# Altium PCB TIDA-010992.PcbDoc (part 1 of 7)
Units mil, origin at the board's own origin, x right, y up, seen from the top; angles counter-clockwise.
Board outline 2810.81 x 2427 mil, 8 copper layers (L01-TOP, L02-GND, L03-SIG, L04-GND, L05-PWR, L06-SIG, L07-GND, L08-BOTTOM), stack 61.9 mil thick; 521 components, 377 nets, 1545 pads, 874 vias.
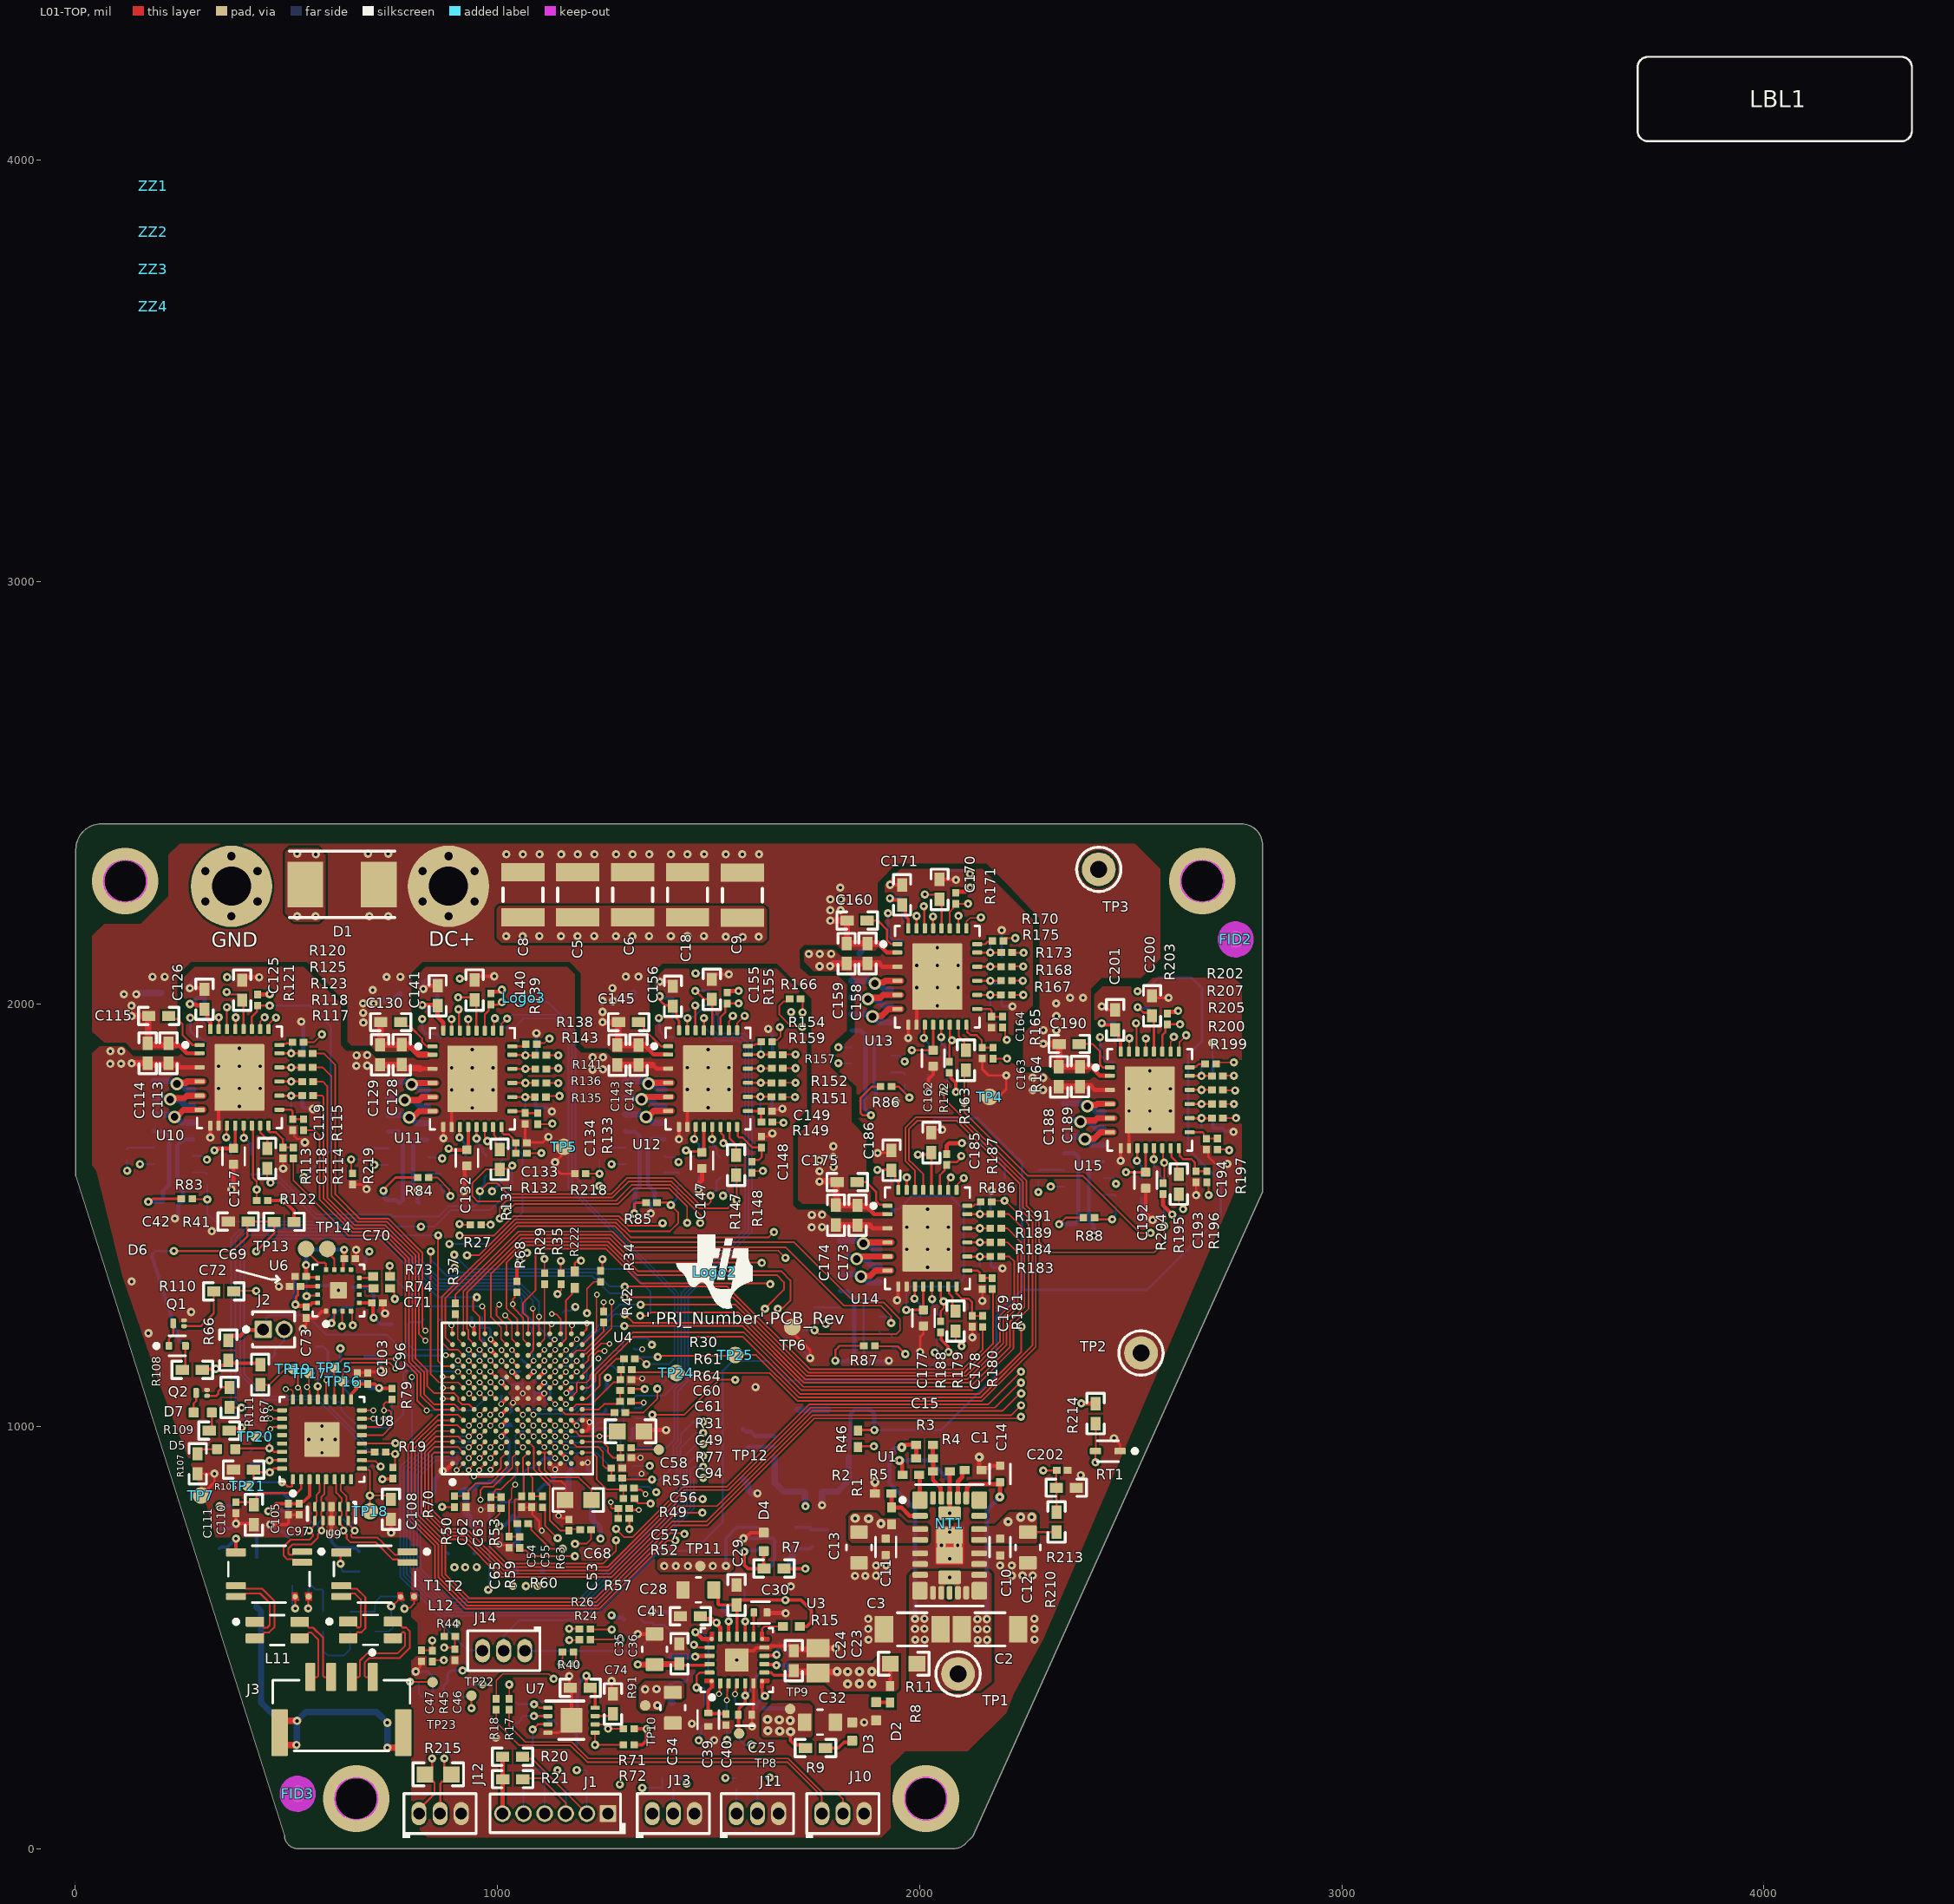
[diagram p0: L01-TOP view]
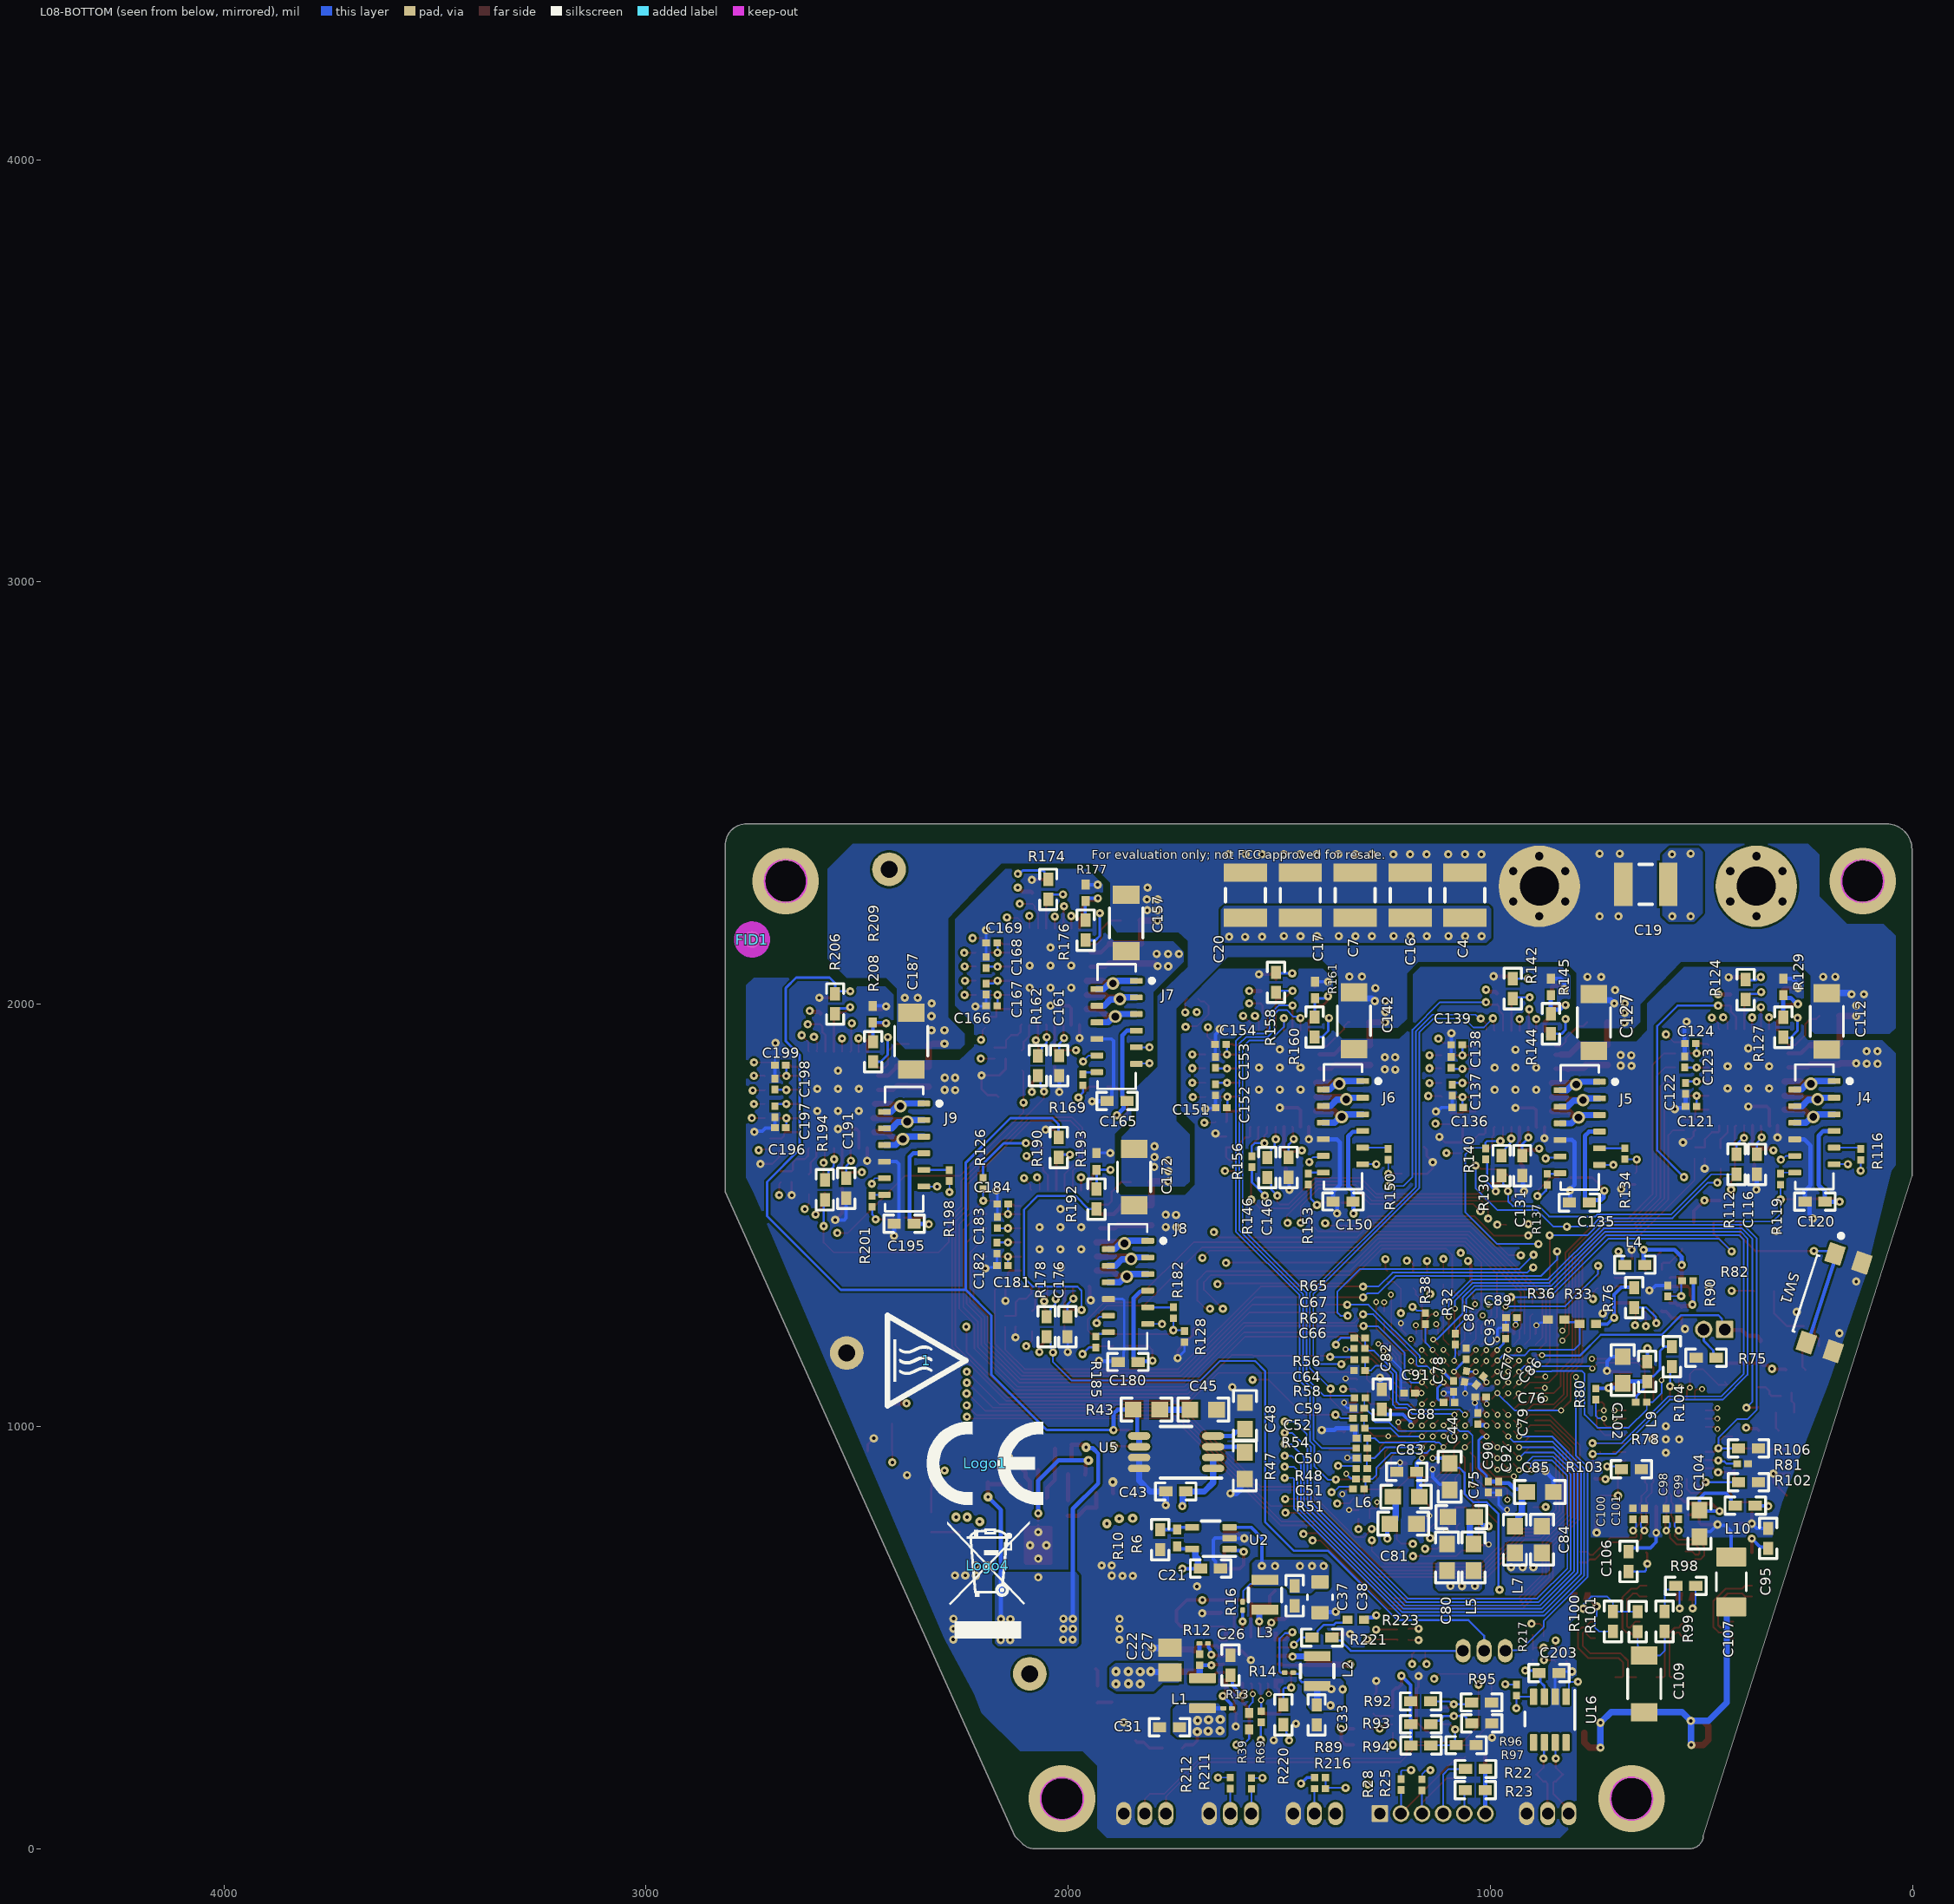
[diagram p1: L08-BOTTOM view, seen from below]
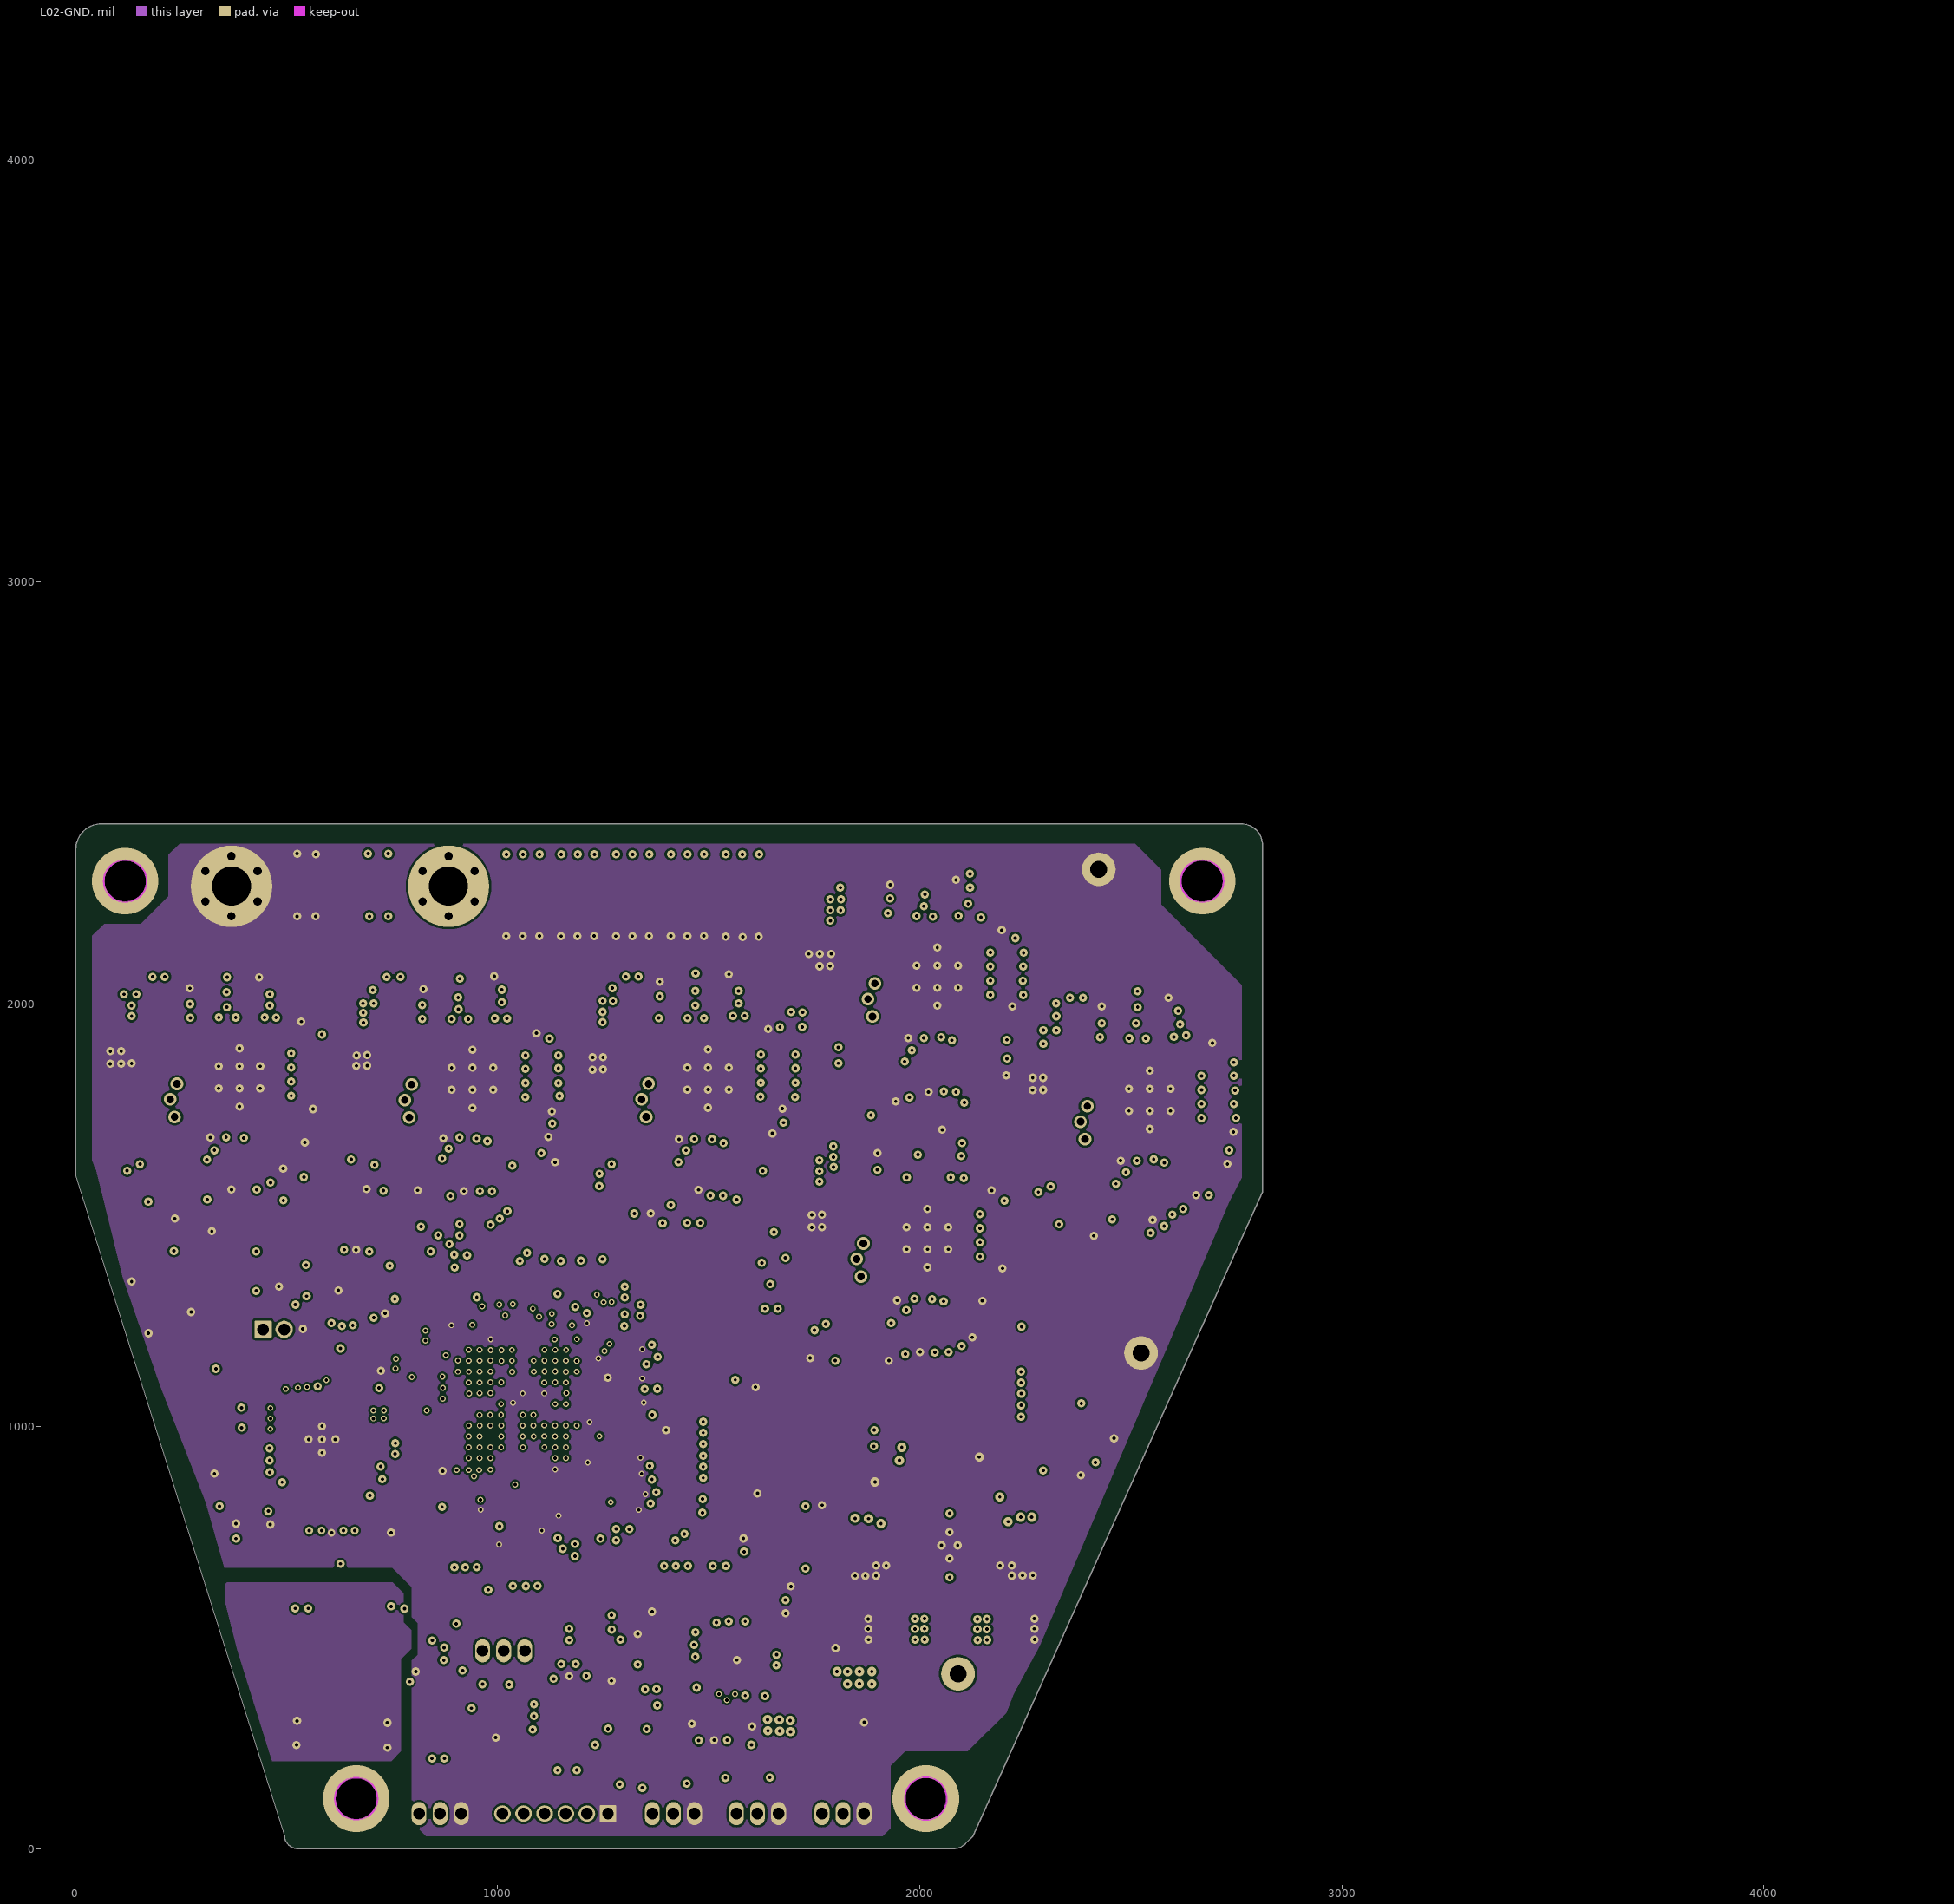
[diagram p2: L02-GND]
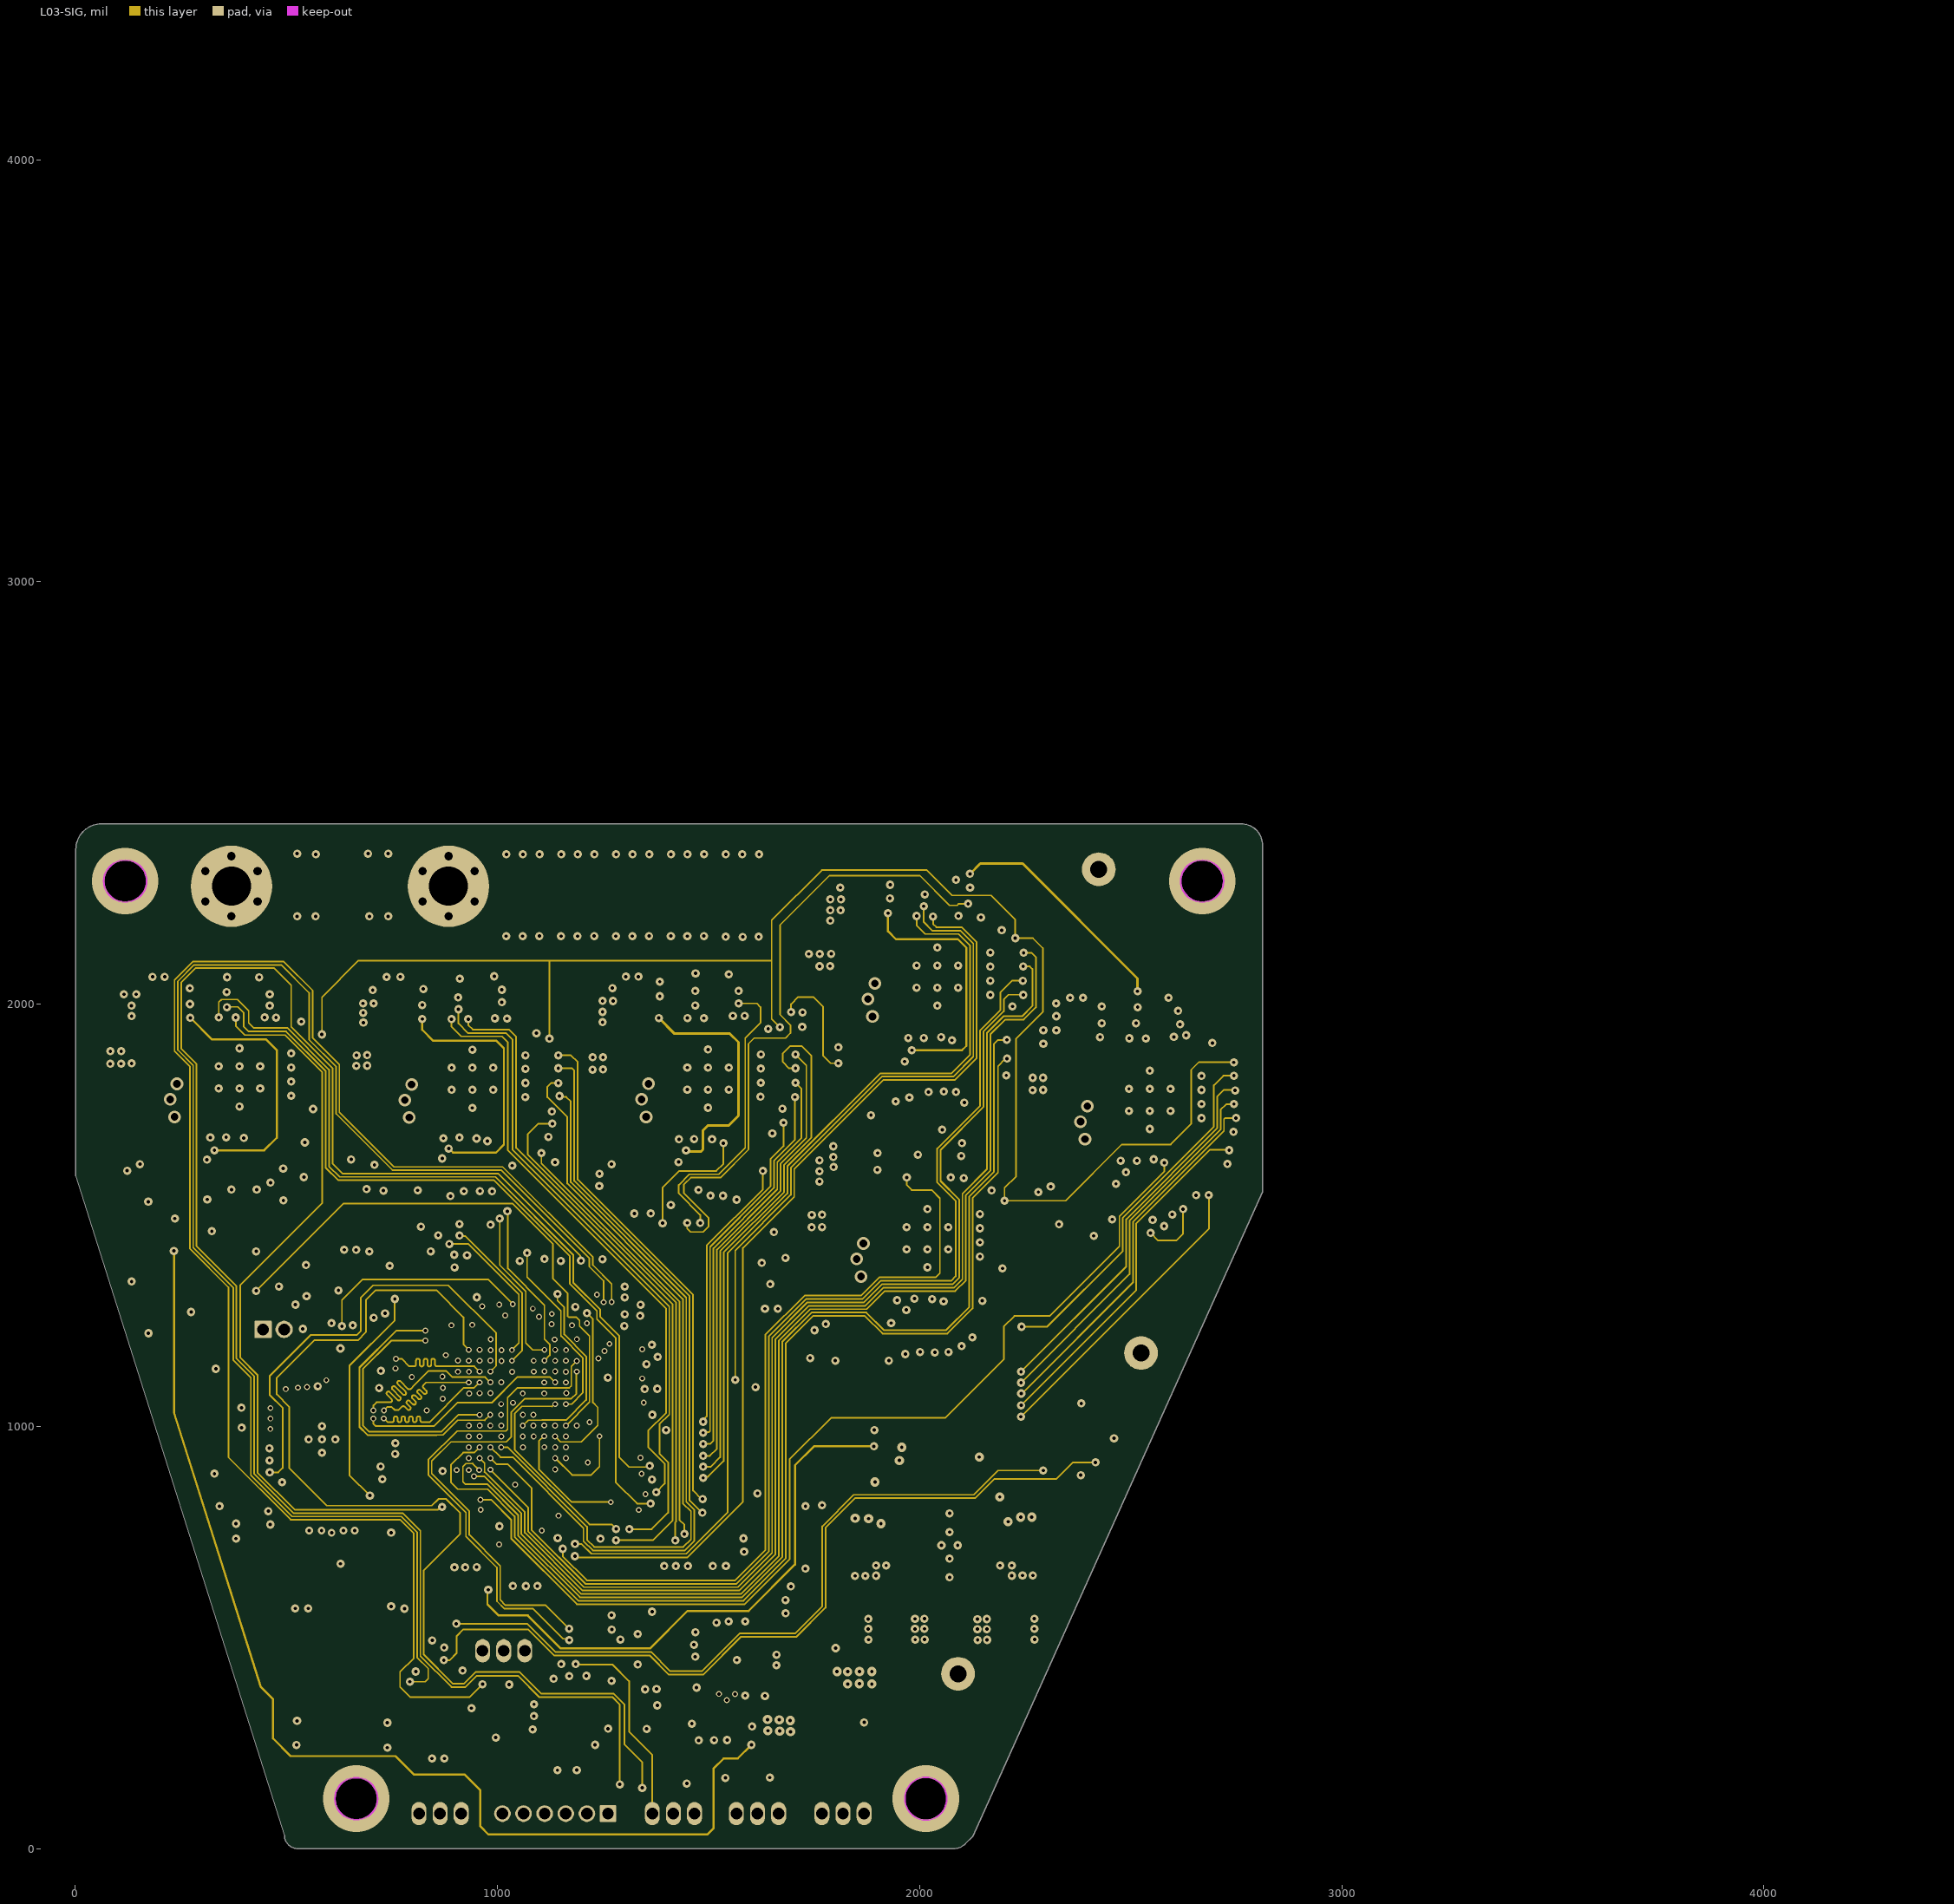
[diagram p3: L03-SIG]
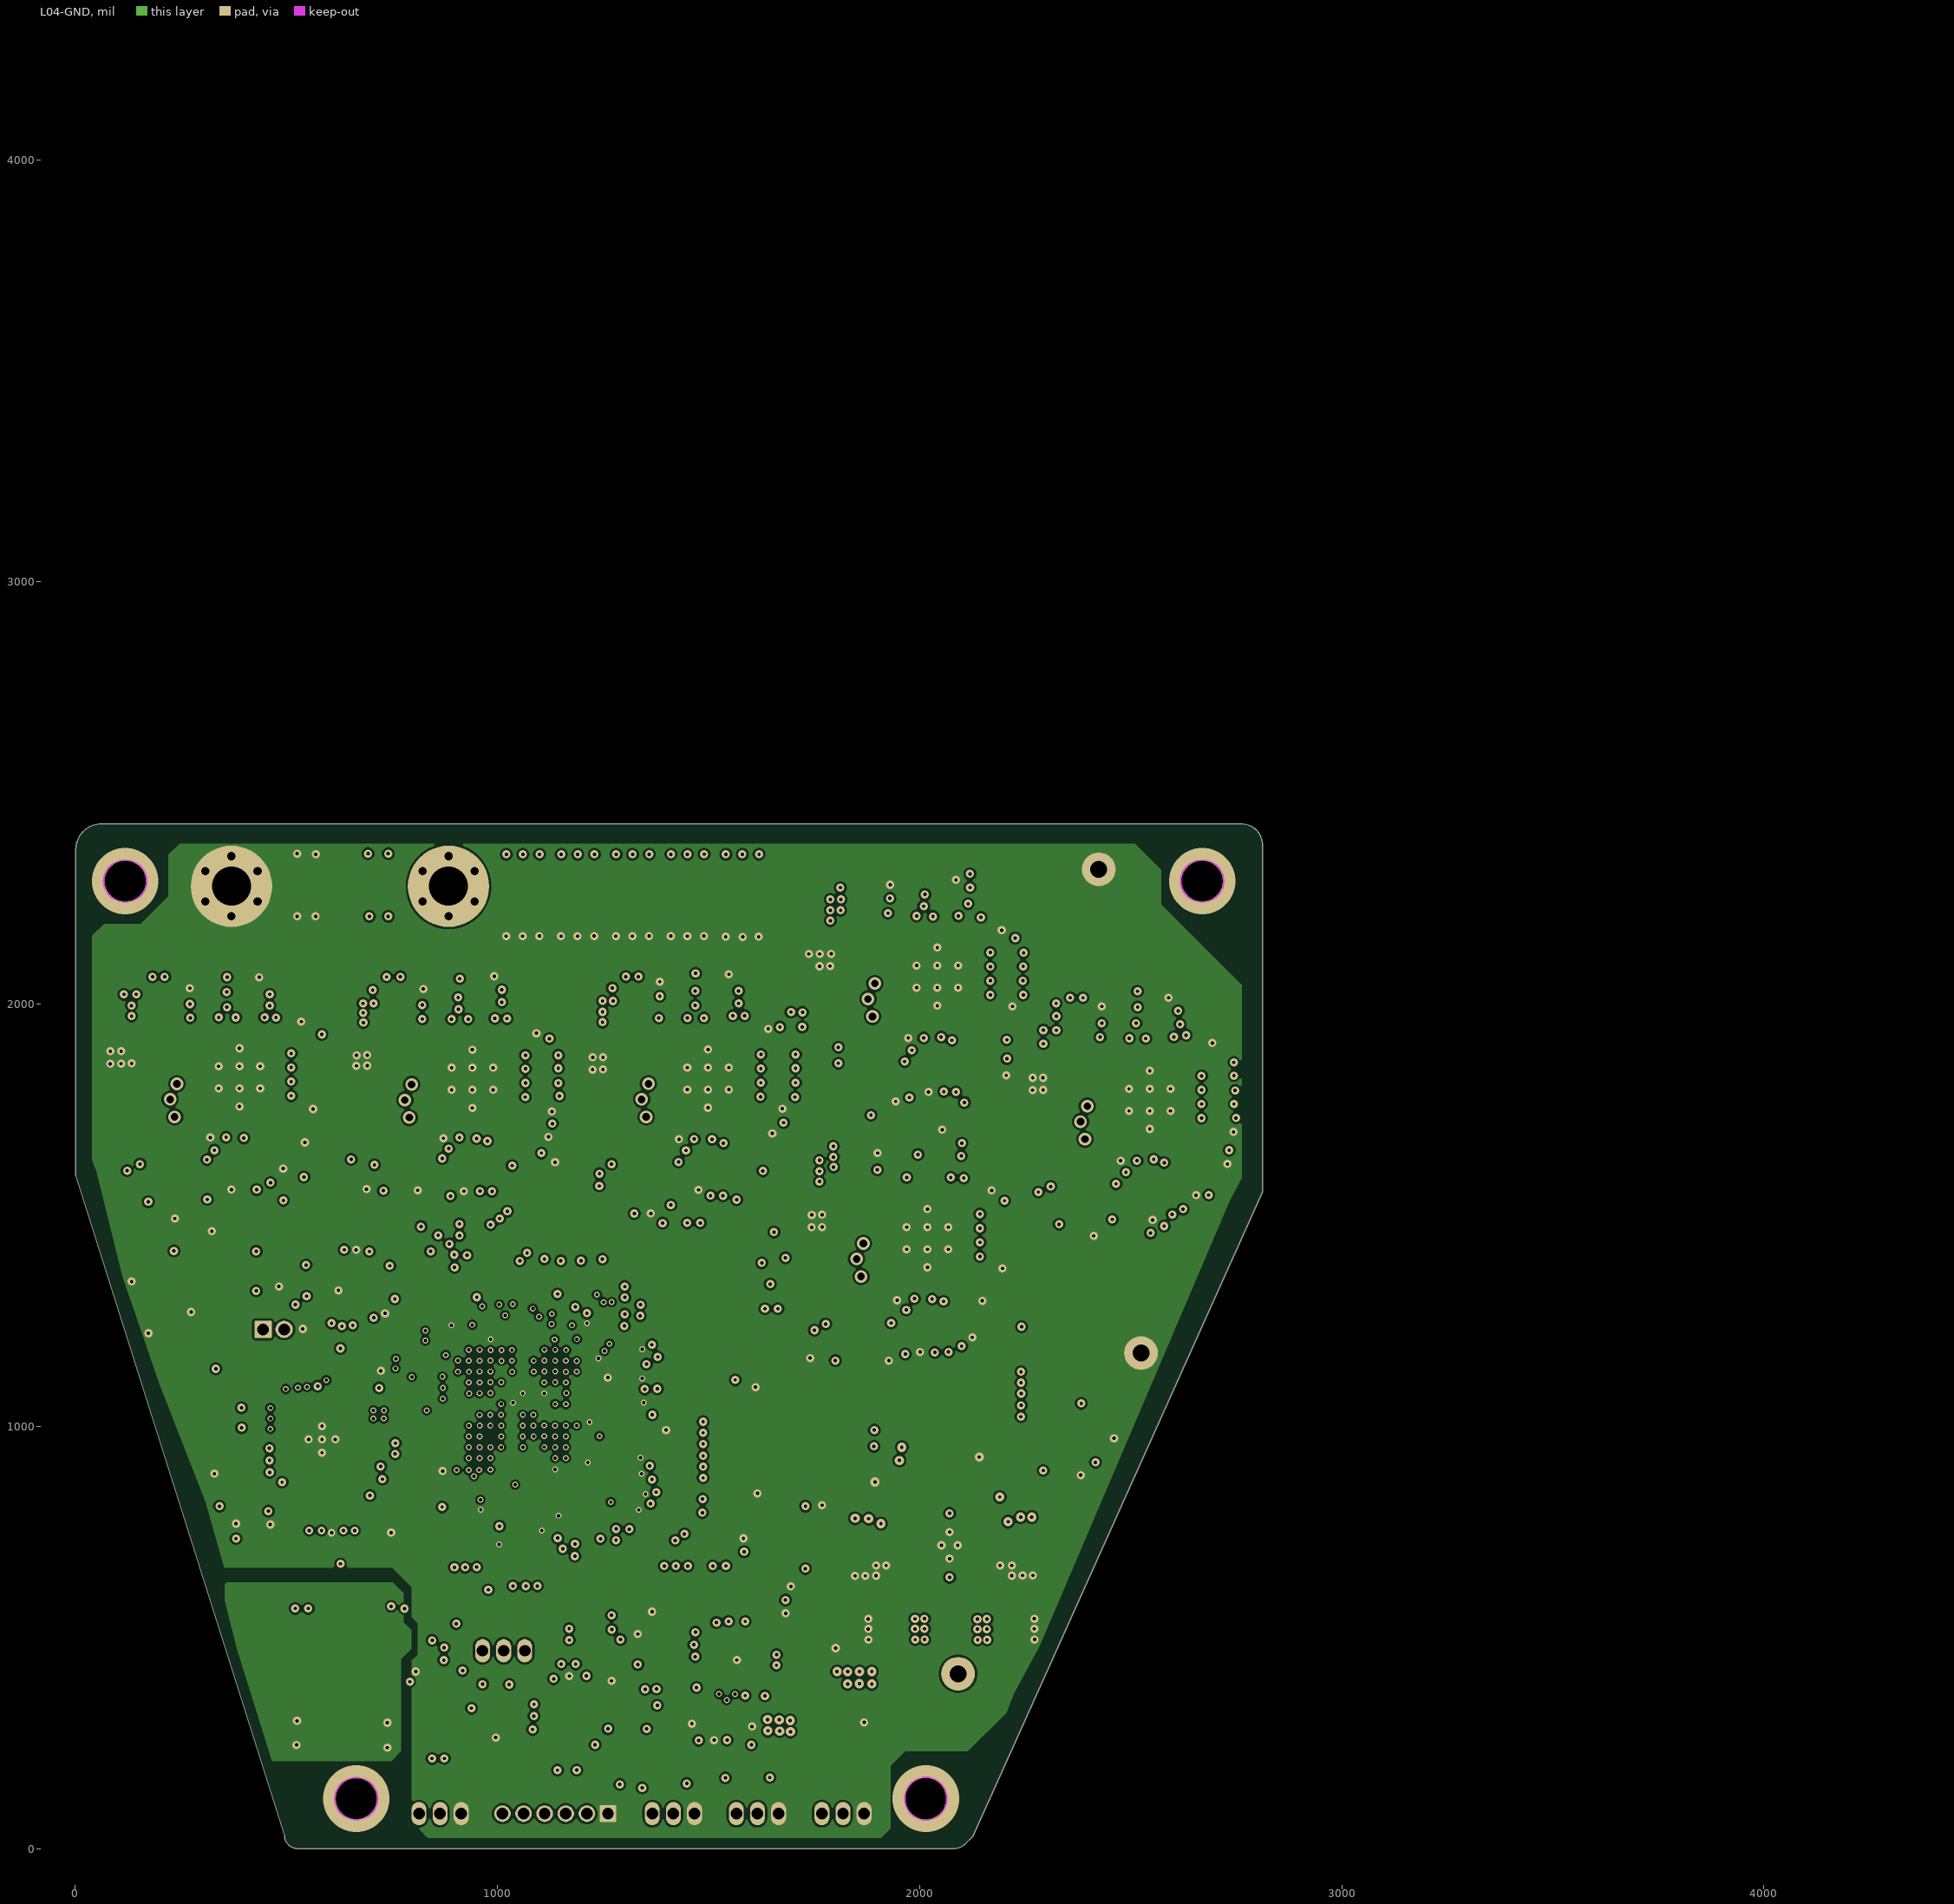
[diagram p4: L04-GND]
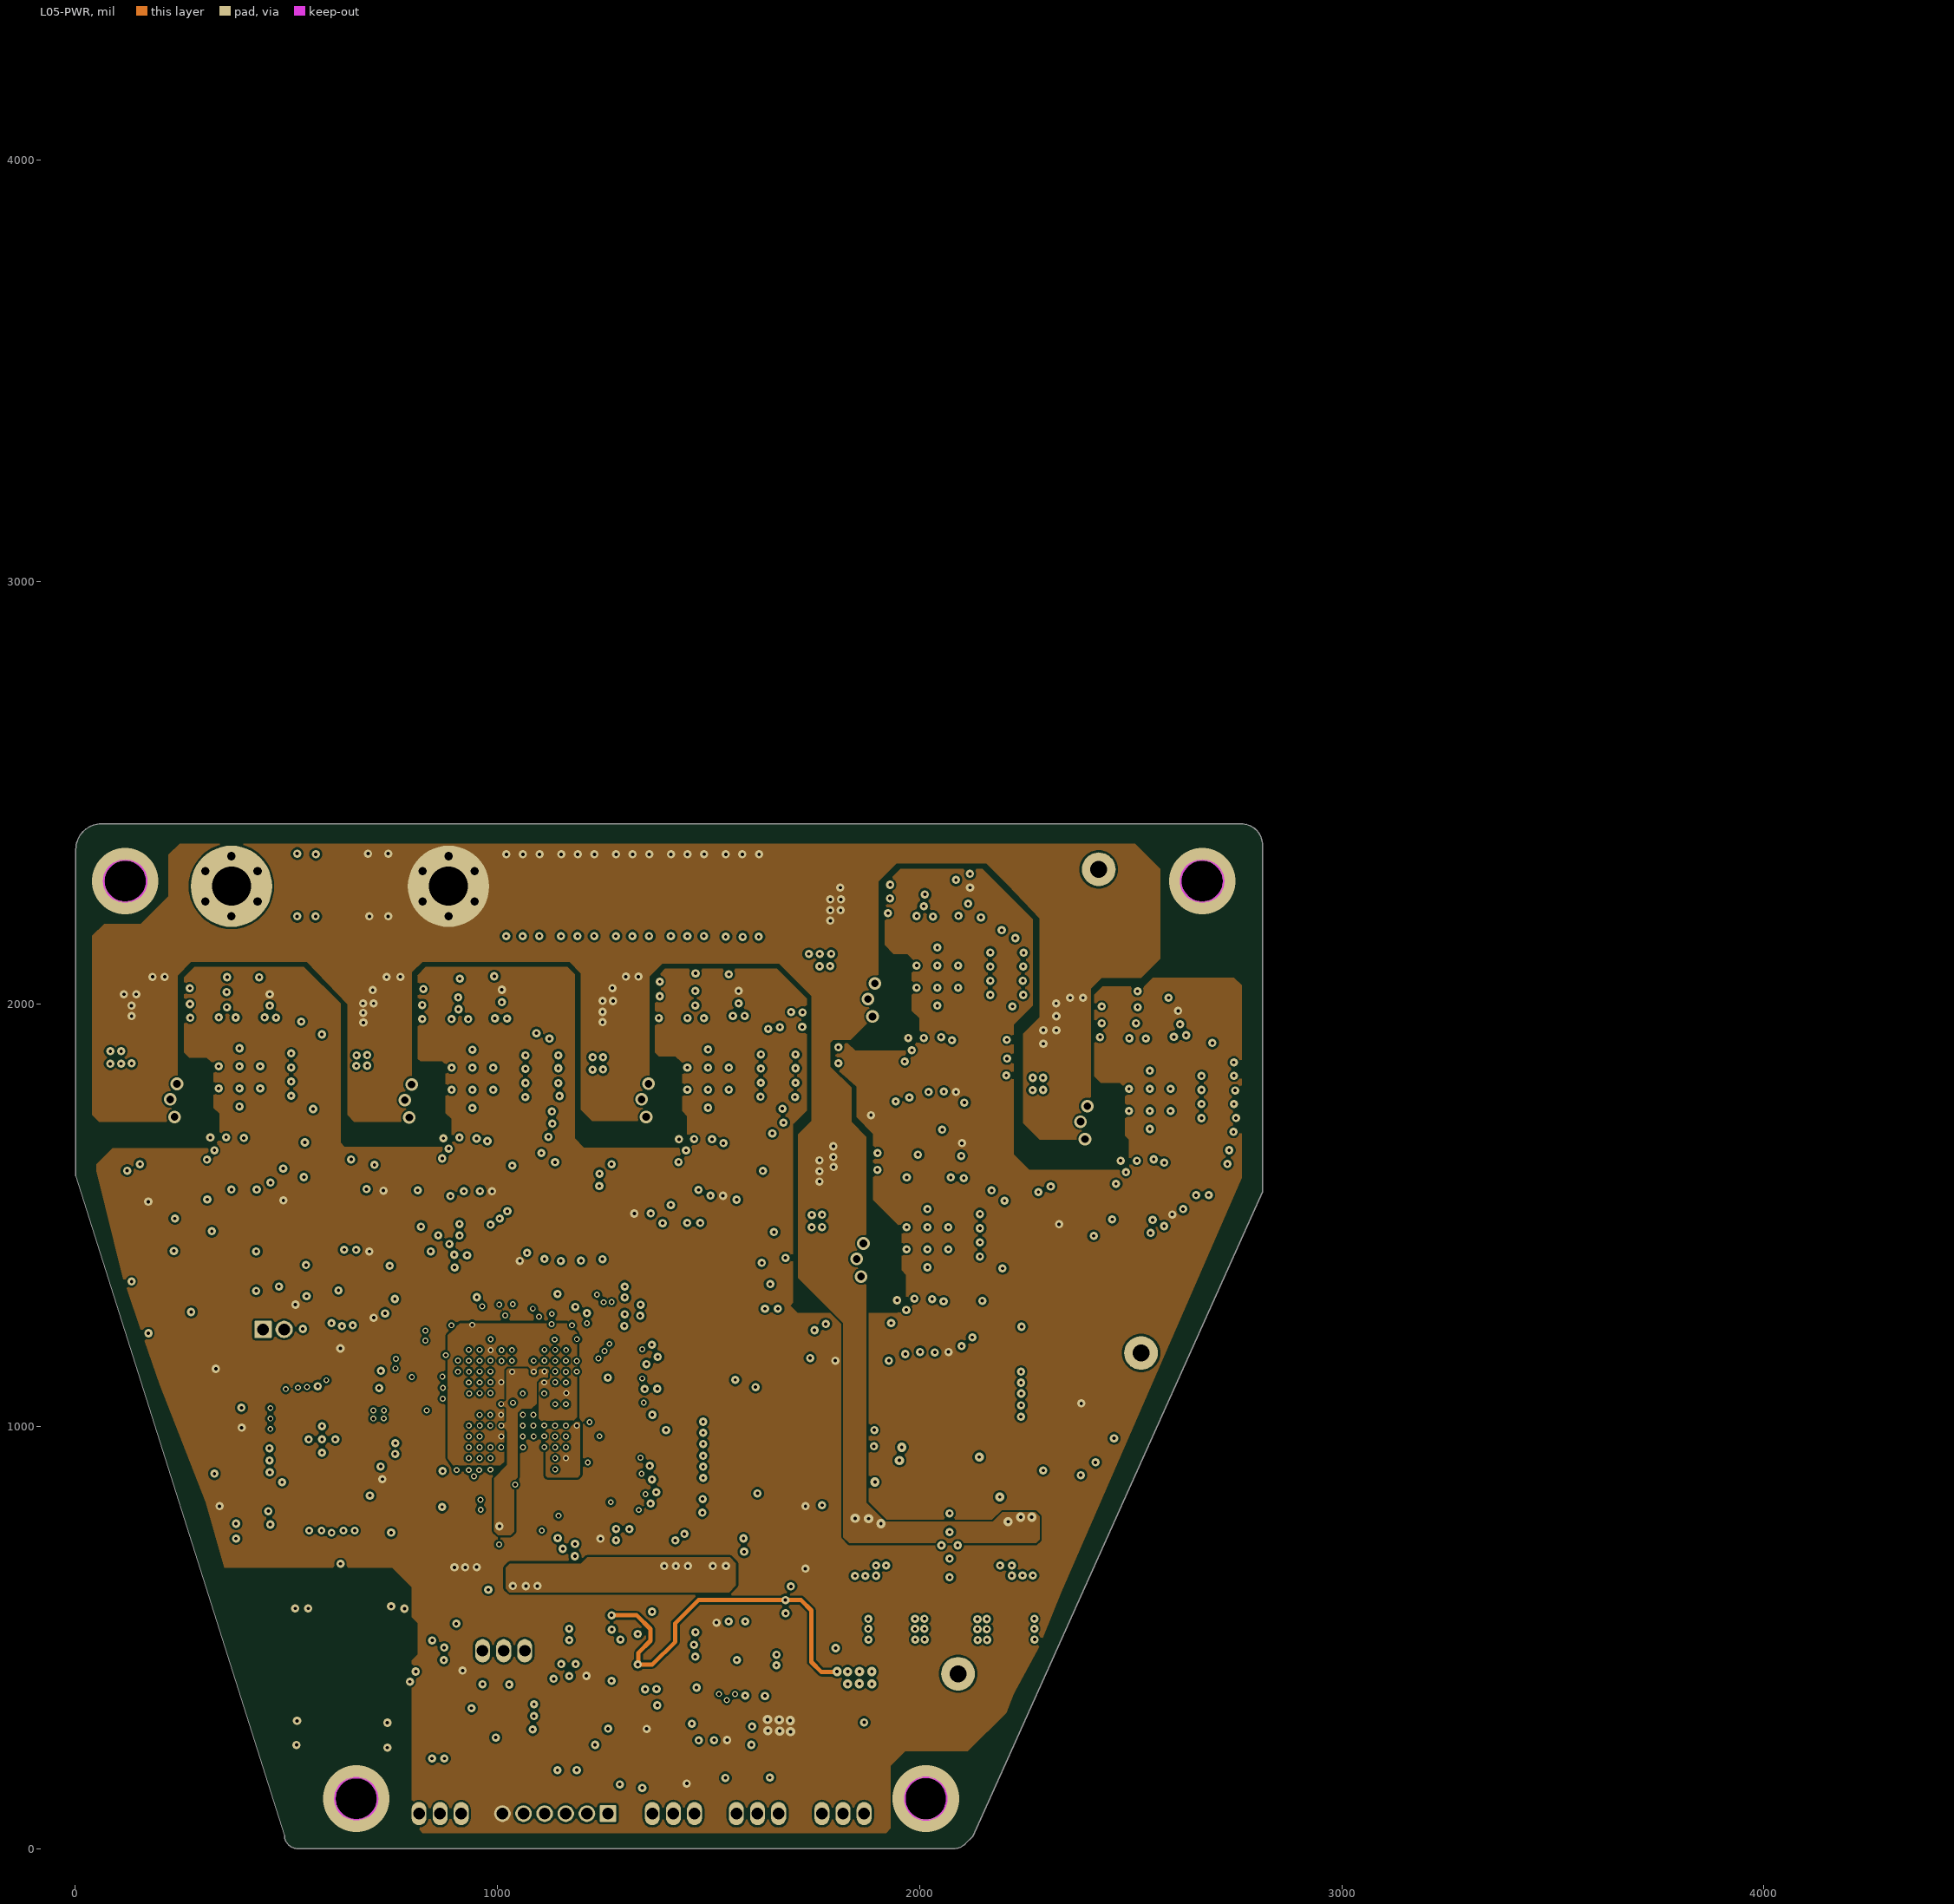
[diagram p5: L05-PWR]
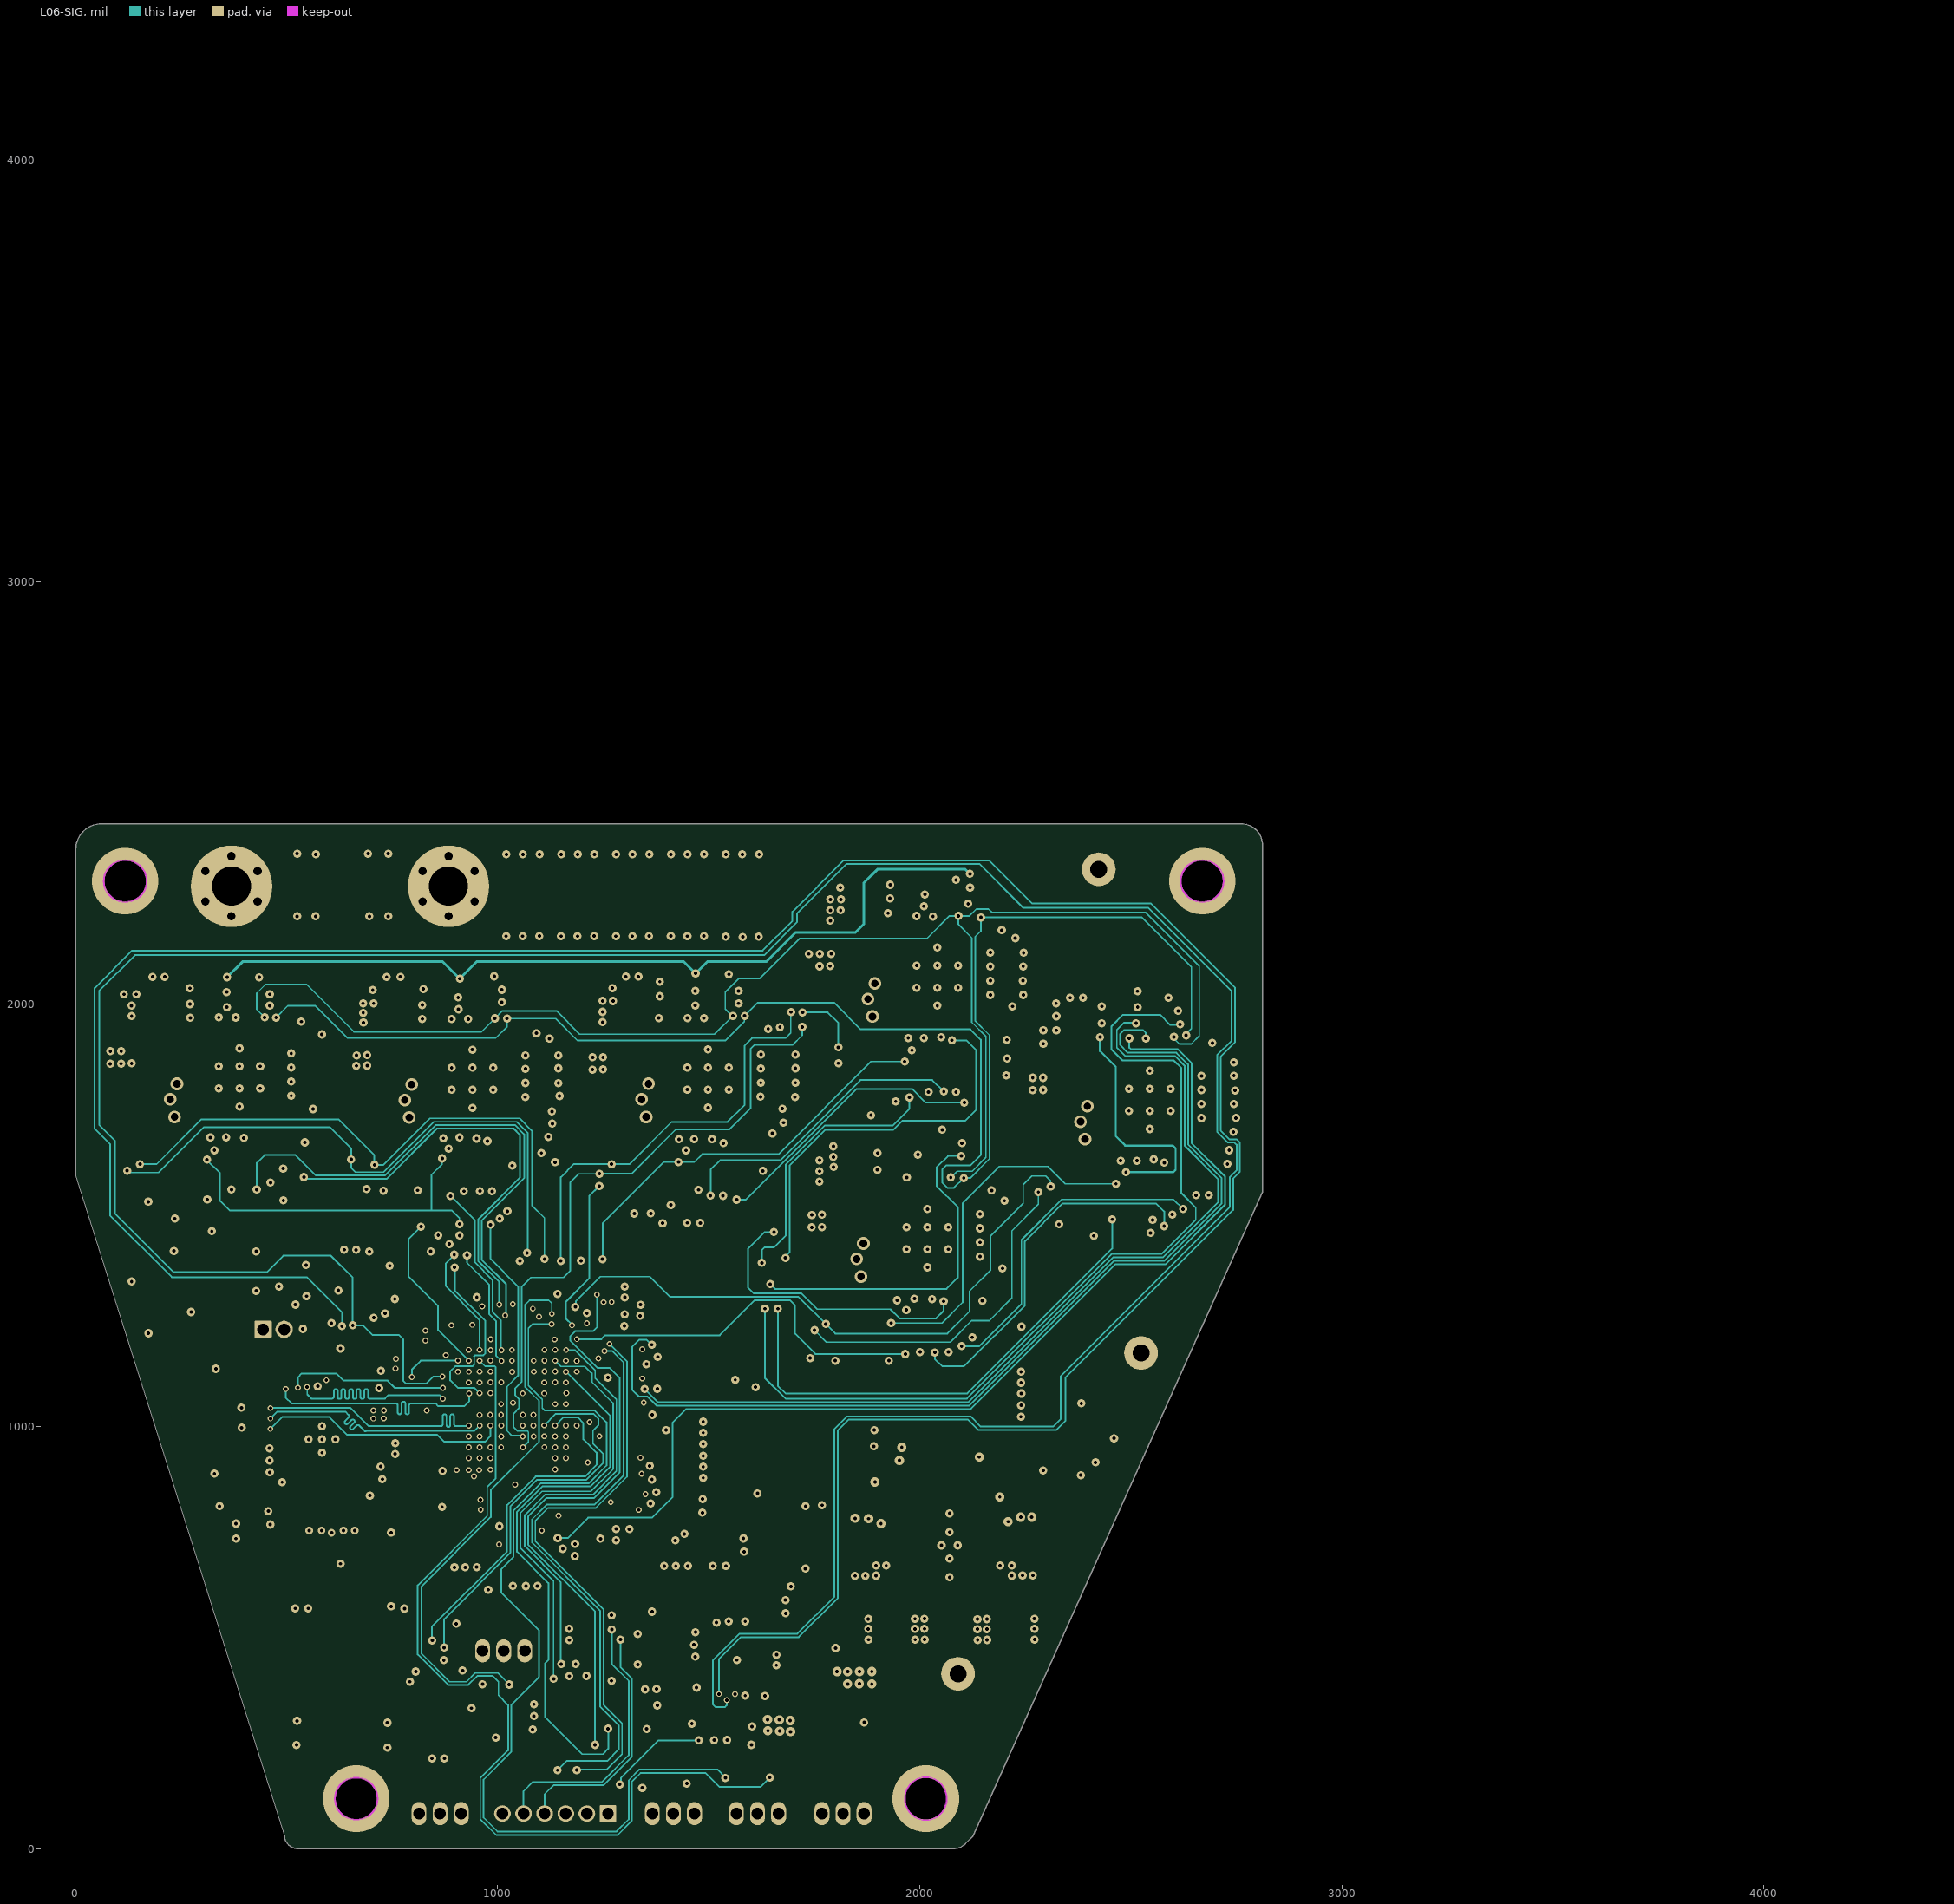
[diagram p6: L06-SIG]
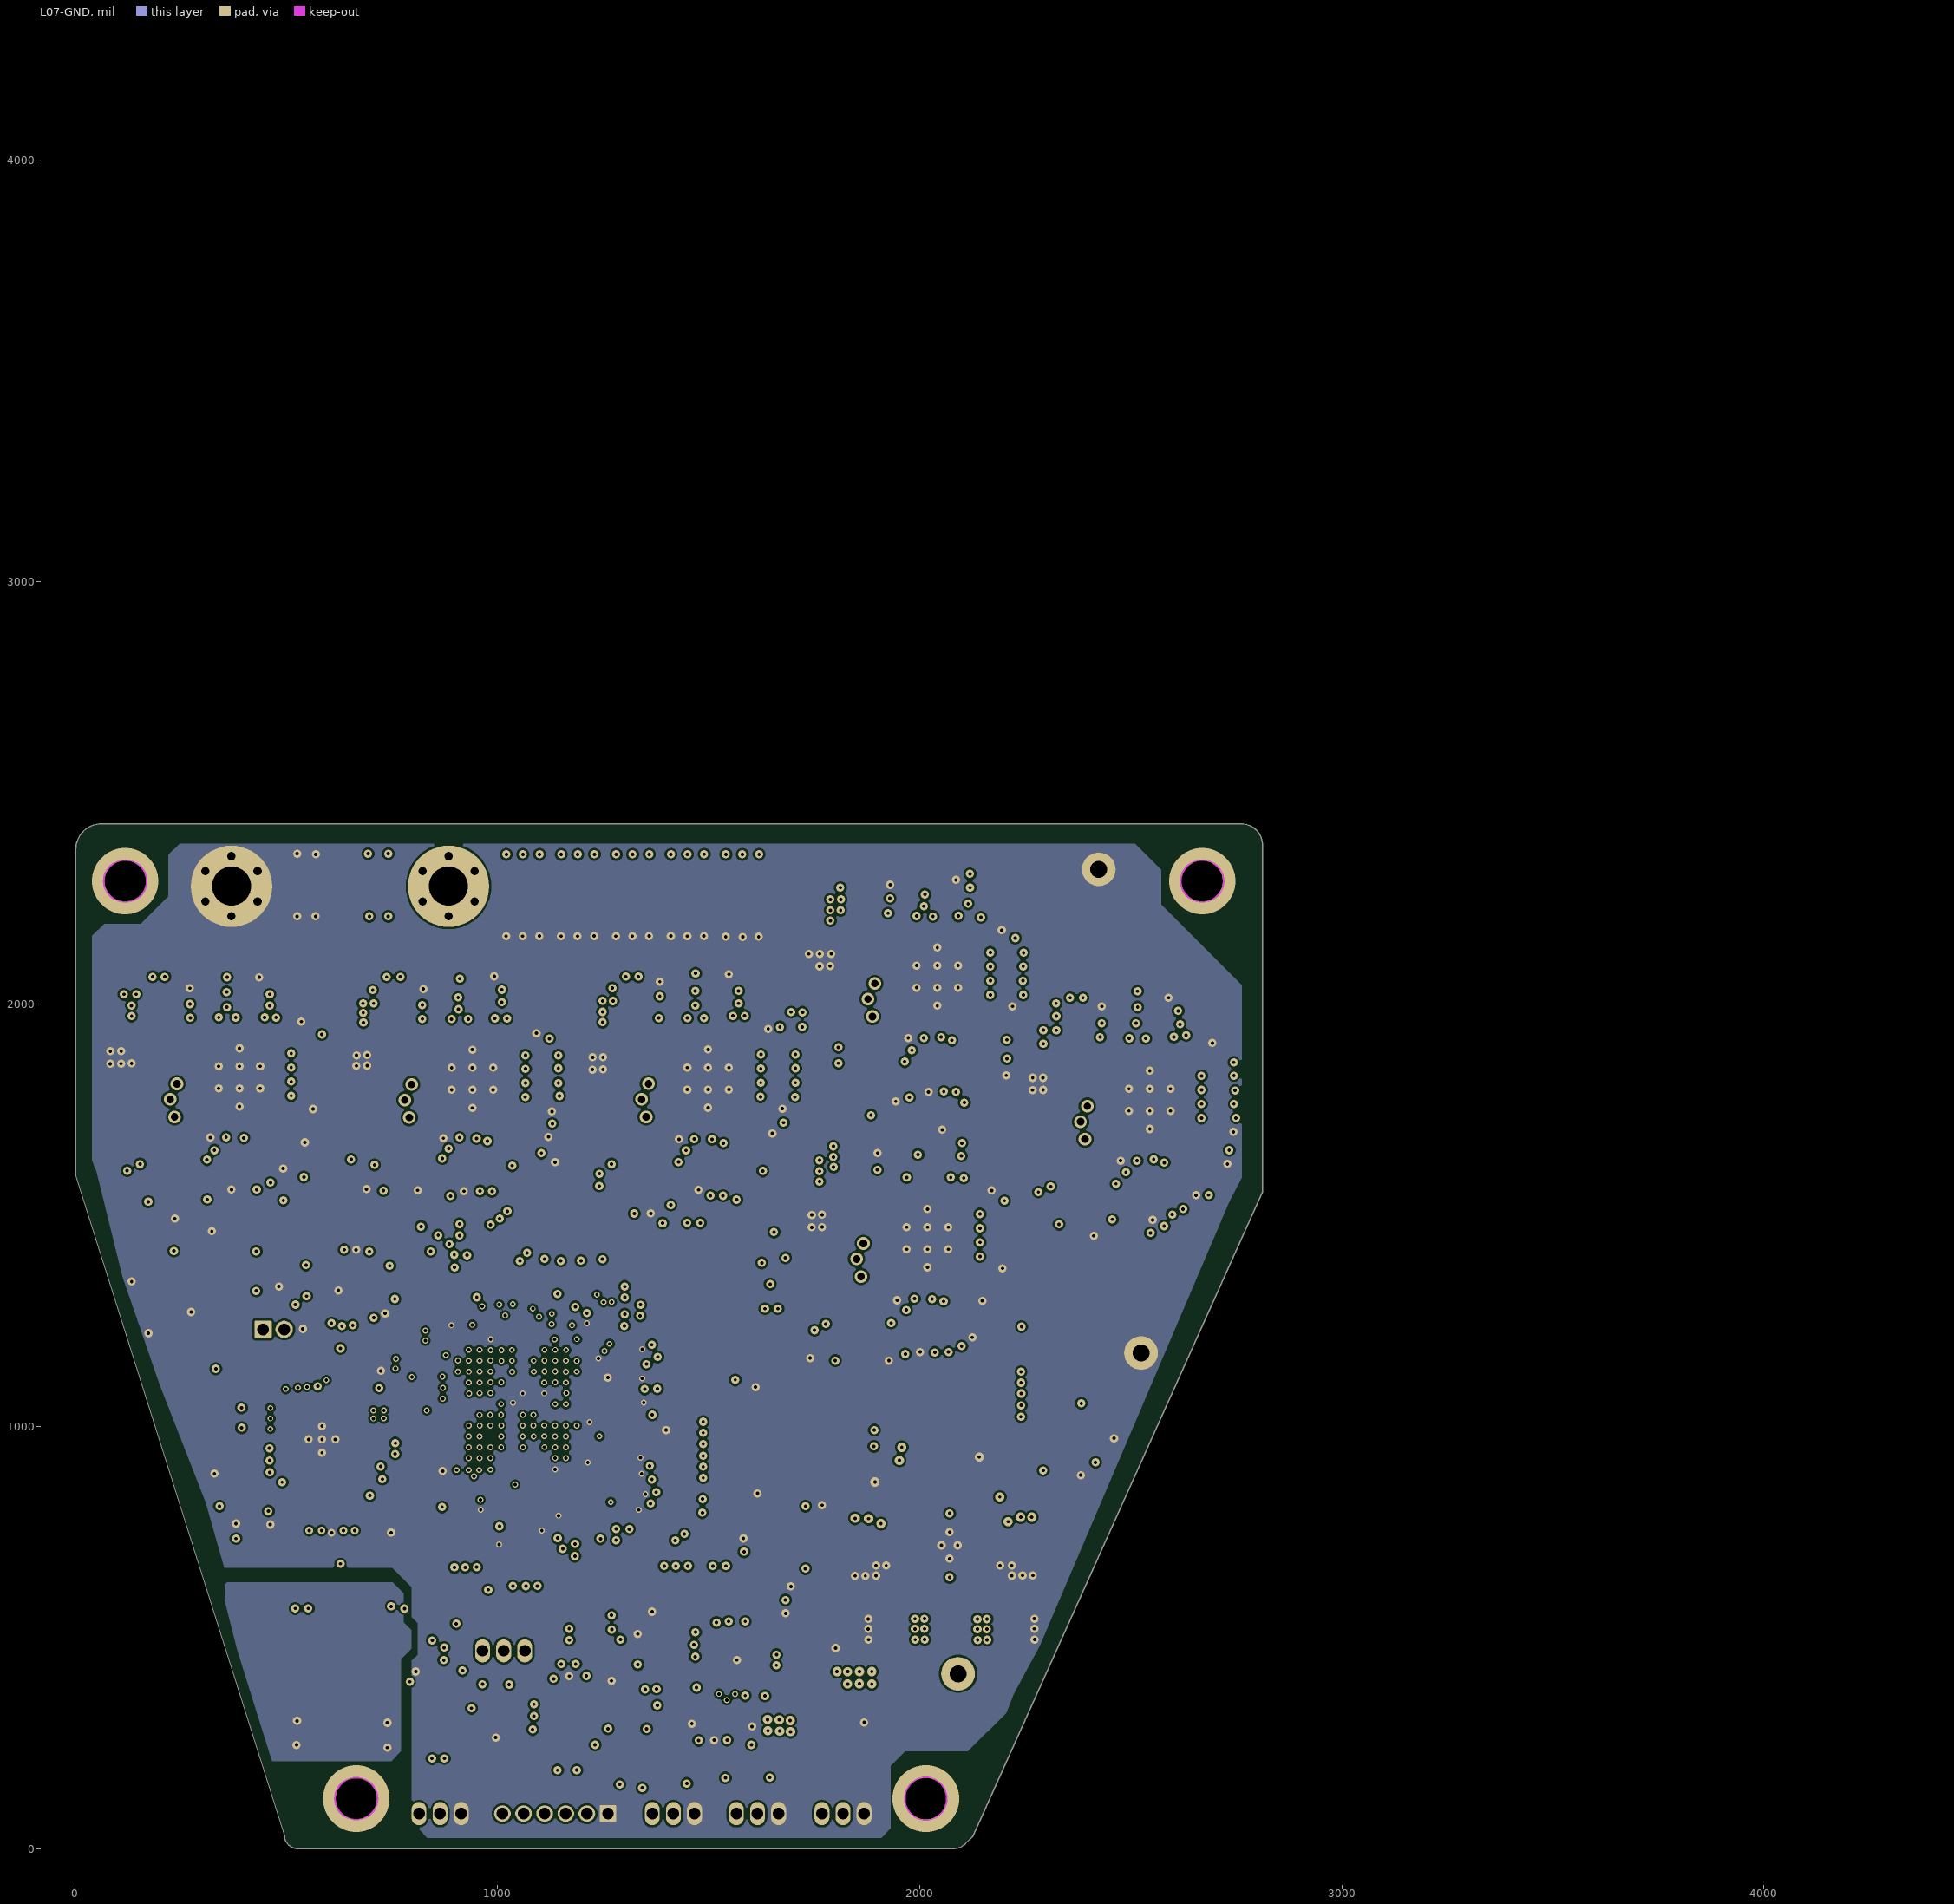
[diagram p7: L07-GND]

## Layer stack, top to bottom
Top Solder: solder mask 0.4, Solder Resist, Dk 3.5
L01-TOP: signal copper 1.4
Dielectric 1: prepreg 3.3, FR-4 370, Dk 4.2
L02-GND: signal copper 1.4
Dielectric 2: core 5, FR-4 370, Dk 4.3
L03-SIG: signal copper 1.4
Dielectric 3: prepreg 9.8, FR-4 370, Dk 4.1
L04-GND: signal copper 1.4
Dielectric 4: core 14.5, FR-4 370, Dk 4.2
L05-PWR: signal copper 1.4
Dielectric 5: prepreg 9.8, FR-4 370, Dk 4.1
L06-SIG: signal copper 1.4
Dielectric 6: core 5, FR-4 370, Dk 4.3
L07-GND: signal copper 1.4
Dielectric 7: prepreg 3.3, FR-4 370, Dk 4.2
L08-BOTTOM: signal copper 1.4
Bottom Solder: solder mask 0.4, Solder Resist, Dk 3.5

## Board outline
526.76,0 cw(c526.76,31.41) 495.35,31.41 1.19,1592.72 1.19,2366.47 cw(c61.71,2366.47) 61.71,2427 2739,2427 2762,2427 cw(c2762,2377) 2812,2377 2811.97,1555 2126,29 2108.31,11.31 cw(c2081,38.63) 2081,0 2034.41,0 529,0
cut-out: 2669.29,2240.16 cw(c2669.29,2291.34) 2618.11,2291.34 cw(c2669.29,2291.34) 2669.29,2342.52 cw(c2669.29,2291.34) 2720.47,2291.34 cw(c2669.29,2291.34)
cut-out: 1963.39,118.11 ccw(c2014.57,118.11) 2014.57,66.93 ccw(c2014.57,118.11) 2065.75,118.11 ccw(c2014.57,118.11) 2014.57,169.29 ccw(c2014.57,118.11)
cut-out: 118.11,2240.16 cw(c118.11,2291.34) 66.93,2291.34 cw(c118.11,2291.34) 118.11,2342.52 cw(c118.11,2291.34) 169.29,2291.34 cw(c118.11,2291.34)
cut-out: 665.35,66.93 cw(c665.35,118.11) 614.17,118.11 cw(c665.35,118.11) 665.35,169.29 cw(c665.35,118.11) 716.54,118.11 cw(c665.35,118.11)
cut-out: 2669.29,2240.16 cw(c2669.29,2291.34) 2618.11,2291.34 cw(c2669.29,2291.34) 2669.29,2342.52 cw(c2669.29,2291.34) 2720.47,2291.34 cw(c2669.29,2291.34)
cut-out: 1963.39,118.11 ccw(c2014.57,118.11) 2014.57,66.93 ccw(c2014.57,118.11) 2065.75,118.11 ccw(c2014.57,118.11) 2014.57,169.29 ccw(c2014.57,118.11)
cut-out: 118.11,2240.16 cw(c118.11,2291.34) 66.93,2291.34 cw(c118.11,2291.34) 118.11,2342.52 cw(c118.11,2291.34) 169.29,2291.34 cw(c118.11,2291.34)
cut-out: 665.35,66.93 cw(c665.35,118.11) 614.17,118.11 cw(c665.35,118.11) 665.35,169.29 cw(c665.35,118.11) 716.54,118.11 cw(c665.35,118.11)
cut-out: 2669.29,2242.13 cw(c2669.29,2291.34) 2620.08,2291.34 cw(c2669.29,2291.34) 2669.29,2340.55 cw(c2669.29,2291.34) 2718.5,2291.34 cw(c2669.29,2291.34)
cut-out: 1965.35,118.11 ccw(c2014.57,118.11) 2014.57,68.9 ccw(c2014.57,118.11) 2063.78,118.11 ccw(c2014.57,118.11) 2014.57,167.32 ccw(c2014.57,118.11)
cut-out: 118.11,2242.13 cw(c118.11,2291.34) 68.9,2291.34 cw(c118.11,2291.34) 118.11,2340.55 cw(c118.11,2291.34) 167.32,2291.34 cw(c118.11,2291.34)
cut-out: 665.35,68.9 cw(c665.35,118.11) 616.14,118.11 cw(c665.35,118.11) 665.35,167.32 cw(c665.35,118.11) 714.57,118.11 cw(c665.35,118.11)

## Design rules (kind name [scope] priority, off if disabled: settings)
AcuteAngle [All] p1: minimum=4.50000000000000E+0001 checktracksonly=TRUE
AcuteAngle AcuteAngle_poly [InPolygon] p2: minimum=4.50000000000000E+0001 checktracksonly=FALSE
AssemblyTestPointUsage [All] p1: valid=2
BoardOutlineClearance BoardOutlineClearance_USB1 [InComponent('USB1')] p1: gap=0 ignorepadtopadclearanceinfootprint=FALSE
BoardOutlineClearance BoardOutlineClearance_MountingHoles [OnCopper and InComponentClass('Mounting Holes')] p2: gap=40 ignorepadtopadclearanceinfootprint=FALSE
BoardOutlineClearance BoardOutlineClearance_Poly [OnCopper and IsPoly] p3: gap=25 ignorepadtopadclearanceinfootprint=FALSE
BoardOutlineClearance [OnCopper and Not InComponentClass('Logo') and not InComponentClass('FiducialMark') and not InRegion(1000,500,4000,800) and not InPoly] p4: gap=10 ignorepadtopadclearanceinfootprint=FALSE
Clearance Poly [InPolygon] p1: gap=5 ignorepadtopadclearanceinfootprint=FALSE
Clearance "RJ45 pad" [InComponent('RJ1') OR InComponent('RJ2')] p2: gap=5 ignorepadtopadclearanceinfootprint=TRUE except(0: SMDPad-THPad)
Clearance Keepout [((IsTrack Or IsArc) And Not InPoly) And IsFree and IsKeepOut vs ((IsTrack Or IsArc) And Not InPoly) And IsFree and IsKeepOut] p3: gap=5 ignorepadtopadclearanceinfootprint=FALSE
Clearance USB1 [InComponent('USB1') vs OnLayer('Keep-Out Layer')] p4: gap=7.87 ignorepadtopadclearanceinfootprint=FALSE
Clearance ISVIA [ISVIA vs ISVIA] p5: gap=0.2 ignorepadtopadclearanceinfootprint=FALSE
Clearance Clearance_FiducialMark [IsKeepOut and InComponentClass('FiducialMark') vs IsPad and InComponentClass('FiducialMark')] p6: gap=0 ignorepadtopadclearanceinfootprint=FALSE
Clearance Clearance_Boardedge [All vs IsKeepOut] p7: gap=11.81 ignorepadtopadclearanceinfootprint=FALSE
Clearance INPOLYGON [InPolygon] p8: gap=11.91 ignorepadtopadclearanceinfootprint=FALSE
Clearance [All] p9: gap=5 ignorepadtopadclearanceinfootprint=FALSE except(3.7: Arc-Via Track-Via; 4: Arc-Arc Arc-Track Arc-SMDPad Track-Track Track-SMDPad)
ComponentClearance "ComponentClearance_overlay to overlay" [OnBottomSilkscreen vs OnTopSilkscreen] p1: gap=0 collisioncheckmode=3 verticalgap=0 showdistances=FALSE
ComponentClearance ComponentClearance_MountingHoles_FiducialMarks [InComponentClass('Mounting Holes') vs InComponentClass('FiducialMark')] p2: gap=10 collisioncheckmode=3 verticalgap=10 showdistances=FALSE
ComponentClearance ComponentClearance_Shunt [InComponentClass('Header') vs InComponentClass('Shunt')] p3: gap=0 collisioncheckmode=3 verticalgap=0 showdistances=FALSE
ComponentClearance ComponentClearance_Logo [InComponentClass('Logo')] p4: gap=10 collisioncheckmode=3 verticalgap=10 showdistances=FALSE
ComponentClearance ComponentClearance_ScrewToNut [(HasFootprint('NY PMS 440 0025 PH')) vs (HasFootprint('Keystone_1902C'))] p5: gap=5 collisioncheckmode=3 verticalgap=10 showdistances=FALSE
ComponentClearance ComponentClearance_MountingHoles [InComponentClass('Mounting Holes')] p6 off: gap=250 collisioncheckmode=3 verticalgap=100000 showdistances=FALSE
ComponentClearance ComponentClearance_SmallPassives [HasFootprint('0201*') or HasFootprint('0402*') or HasFootprint('0508') or HasFootprint('0603*') or HasFootprint('0612') or HasFootprint('0805*') or HasFootprint('0815*') or HasFootprint('0830*') or HasFootprint('1206*') or HasFootprint('1210*') or HasFootprint('1808*') or HasFootprint('1812*') or HasFootprint('1825*') or HasFootprint('2010*') or HasFootprint('2220*') or HasFootprint('2225*') or HasFootprint('2512*') or HasFootprint('2728*') or HasFootprint('3518*') vs HasFootprint('0201*') or HasFootprint('0402*') or HasFootprint('0508') or HasFootprint('0603*') or HasFootprint('0612') or HasFootprint('0805*') or HasFootprint('0815*') or HasFootprint('0830*') or HasFootprint('1206*') or HasFootprint('1210*') or HasFootprint('1808*') or HasFootprint('1812*') or HasFootprint('1825*') or HasFootprint('2010*') or HasFootprint('2220*') or HasFootprint('2225*') or HasFootprint('2512*') or HasFootprint('2728*') or HasFootprint('3518*')] p7 off: gap=10 collisioncheckmode=3 verticalgap=0 showdistances=FALSE
ComponentClearance ComponentClearance_THtoSMT [IsThruComponent vs IsSMTComponent] p8 off: gap=30 collisioncheckmode=3 verticalgap=30 showdistances=FALSE
ComponentClearance ComponentClearance_THtoTH [IsThruComponent vs IsThruComponent] p9 off: gap=30 collisioncheckmode=3 verticalgap=30 showdistances=FALSE
DiffPairsRouting DiffPairsRouting_100 [All] p1: maxlimit=6.95 minlimit=6.95 mostfreqgap=6.95 toplayer_minwidth=4.25 toplayer_maxwidth=4.25 toplayer_prefwidth=4.25 midlayer1_minwidth=4.25 midlayer1_maxwidth=4.25 midlayer1_prefwidth=4.25 midlayer2_minwidth=4.25 midlayer2_maxwidth=4.25 midlayer2_prefwidth=4.25 midlayer3_minwidth=4.25 midlayer3_maxwidth=4.25 midlayer3_prefwidth=4.25 midlayer4_minwidth=4.25 midlayer4_maxwidth=4.25 midlayer4_prefwidth=4.25 midlayer5_minwidth=4.25 midlayer5_maxwidth=4.25 midlayer5_prefwidth=4.25 midlayer6_minwidth=4.25 midlayer6_maxwidth=4.25 midlayer6_prefwidth=4.25 bottomlayer_minwidth=4.25 bottomlayer_maxwidth=4.25 bottomlayer_prefwidth=4.25 maxuncoupledlength=500
DiffPairsRouting DiffPairsRouting_120 [InDifferentialPairClass('diff120')] p2 off: maxlimit=6.8 minlimit=6.8 mostfreqgap=6.8 toplayer_minwidth=4.1 toplayer_maxwidth=4.1 toplayer_prefwidth=4.1 midlayer1_minwidth=4.1 midlayer1_maxwidth=4.1 midlayer1_prefwidth=4.1 midlayer2_minwidth=4.1 midlayer2_maxwidth=4.1 midlayer2_prefwidth=4.1 midlayer3_minwidth=4.1 midlayer3_maxwidth=4.1 midlayer3_prefwidth=4.1 midlayer4_minwidth=4.1 midlayer4_maxwidth=4.1 midlayer4_prefwidth=4.1 midlayer5_minwidth=4.1 midlayer5_maxwidth=4.1 midlayer5_prefwidth=4.1 midlayer6_minwidth=4.1 midlayer6_maxwidth=4.1 midlayer6_prefwidth=4.1 bottomlayer_minwidth=4.1 bottomlayer_maxwidth=4.1 bottomlayer_prefwidth=4.1 maxuncoupledlength=1000
FabricationTestPointUsage TestPointUsage [All] p1: valid=2 allowmultiple=FALSE
FabricationTestpoint Testpoint [All] p1: side=3 testpointundercomponent=TRUE minsize=40 maxsize=100 preferedsize=60 minholesize=0 maxholesize=40 preferedholesize=32 testpointgrid=1 allowsidetop=TRUE allowsidebottom=TRUE usegrid=TRUE gridtolerance=0.01
FanoutControl Fanout_LCC [IsLCC] p1: bgadir=Out bgaviamode=Centered fanoutstyle=Auto fanoutdirection=Alternating viagrid=1 // Fanout_LCC (Default Rule)
FanoutControl Fanout_BGA [IsBGA] p2: bgadir=Out bgaviamode=Centered fanoutstyle=Auto fanoutdirection=Alternating viagrid=1 // Fanout_BGA (Default Rule)
FanoutControl Fanout_Default [All] p4: bgadir=Out bgaviamode=Centered fanoutstyle=Auto fanoutdirection=Alternating viagrid=1 // Fanout_Default (Default Rule)
FanoutControl Fanout_Small [(CompPinCount < 5)] p5: bgadir=Out bgaviamode=Centered fanoutstyle=Auto fanoutdirection=OutThenIn viagrid=1 // Fanout_Small (Default Rule)
HoleSize [All] p1: absolutevalues=TRUE maxlimit=251 minlimit=7.87 maxpercent=80.000 minpercent=20.000
HoleToHoleClearance HoleToHoleClearance_USB1 [InComponent('USB1') vs InComponent('USB1')] p1: gap=0 allowstackedmicrovias=TRUE
HoleToHoleClearance [All] p2: gap=10 allowstackedmicrovias=TRUE
MatchedLengths FSIRX [InNetClass('FSIRX')] p1: tolerance=25 checknetsindiffpair=FALSE checkdiffpairvsdiffpair=TRUE checkxsignals=TRUE checkothers=TRUE
MatchedLengths FSITX [InNetClass('FSITX')] p2: tolerance=25 checknetsindiffpair=FALSE checkdiffpairvsdiffpair=TRUE checkxsignals=TRUE checkothers=TRUE
MinimumAnnularRing MinimumAnnularRing_ThermalPadVias [IsVia and InAnyComponent] p1: minimumring=3
MinimumAnnularRing MinimumAnnularRing_usb1 [InComponent('USB1')] p2: minimumring=0
MinimumAnnularRing [All] p3: minimumring=3
MinimumSolderMaskSliver MinimumSolderMaskSliver_Logo [InComponentClass('Logo') vs InComponentClass('Logo')] p1: minsoldermaskwidth=0.7
MinimumSolderMaskSliver [All] p2: minsoldermaskwidth=3
PlaneClearance PlaneClearance_Via [IsVia] p1: clearance=10
PlaneClearance [All] p2: clearance=10
PlaneConnect [All] p1: planeconnectstyle=Relief reliefexpansion=10 reliefentries=4 reliefconductorwidth=25 reliefairgap=10
PolygonConnect PolygonConnect_via [IsVia] p1: connectstyle=Direct reliefconductorwidth=10 reliefentries=4 polygonreliefangle="90 Angle" airgapwidth=10
PolygonConnect PolygonConnect_GND_under_device [Name = 'TOP_SIGNAL_GND_P125'] p2: connectstyle=Direct reliefconductorwidth=10 reliefentries=4 polygonreliefangle="90 Angle" airgapwidth=5
PolygonConnect PolygonConnect_via_VDD [Name = 'PWR_VDD_P012'] p3: thpad.connectstyle=Relief thpad.reliefconductorwidth=10 thpad.reliefentries=4 thpad.polygonreliefangle="90 Angle" thpad.airgapwidth=5 smdpad.connectstyle=Relief smdpad.reliefconductorwidth=10 smdpad.reliefentries=4 smdpad.polygonreliefangle="90 Angle" smdpad.airgapwidth=5 via.connectstyle=Direct via.reliefconductorwidth=10 via.reliefentries=4 via.polygonreliefangle="90 Angle" via.airgapwidth=5
PolygonConnect PolygonConnect_via_VDDIO [Name = 'PWR_VDDIO_P129'] p4: thpad.connectstyle=Relief thpad.reliefconductorwidth=10 thpad.reliefentries=4 thpad.polygonreliefangle="90 Angle" thpad.airgapwidth=5 smdpad.connectstyle=Relief smdpad.reliefconductorwidth=10 smdpad.reliefentries=4 smdpad.polygonreliefangle="90 Angle" smdpad.airgapwidth=5 via.connectstyle=Direct via.reliefconductorwidth=10 via.reliefentries=4 via.polygonreliefangle="90 Angle" via.airgapwidth=5
PolygonConnect [All] p5: connectstyle=Direct reliefconductorwidth=10 reliefentries=4 polygonreliefangle="90 Angle" airgapwidth=5
RoutingVias ThermalPadVias [IsVia and InAnyComponent] p1: holewidth=8 width=22 viastyle="Through Hole" minholewidth=7.87 minwidth=14 maxholewidth=8 maxwidth=22
RoutingVias [All] p2: holewidth=8 width=22 viastyle="Through Hole" minholewidth=7.87 minwidth=14 maxholewidth=18 maxwidth=30
ShortCircuit ShortCircuit_RJ45 [InComponent('RJ1') And IsThruPin Or InComponent('RJ2') And IsThruPin] p1: allowed=TRUE
ShortCircuit [All] p2: allowed=FALSE
SilkToBoardRegionClearance [Not ((IsComment or IsDesignator) And (Hide <> 'False')) and not InRegion(1000,500,4000,800)] p1:
SilkToSilkClearance SilkToSilkClearance_Pb-FreeLogo [(HasFootprint('Pb-Free_Overlay_Medium') OR HasFootprint('Pb-Free_Overlay_Small')) vs (HasFootprint('Pb-Free_Overlay_Medium') OR HasFootprint('Pb-Free_Overlay_Small'))] p1: silktosilkclearance=0
SilkToSilkClearance [All] p2: silktosilkclearance=3
SilkToSolderMaskClearance SilkToComponentPadClearance [(IsPad or IsFill or IsRegion) and InAnycomponent] p1: minsilkscreentomaskgap=0 clearancetoexposedcopper=TRUE
SilkToSolderMaskClearance "Silk to Solder Mask Opening" [All] p2: minsilkscreentomaskgap=0 clearancetoexposedcopper=TRUE
SolderMaskExpansion [All] p1: expansion=1.97 istentingtop=FALSE
SupplyNets "Schematic Supply Nets_24" [InNet('5V_SYS')] p1: voltage=0.000
SupplyNets "Schematic Supply Nets_23" [InNet('24V')] p2: voltage=0.000
SupplyNets "Schematic Supply Nets_22" [InNet('GVDD5')] p3: voltage=0.000
SupplyNets "Schematic Supply Nets_20" [InNet('VDD')] p4: voltage=0.000
SupplyNets "Schematic Supply Nets_19" [InNet('GVDD4')] p5: voltage=0.000
SupplyNets "Schematic Supply Nets_18" [InNet('GND')] p6: voltage=0.000
SupplyNets "Schematic Supply Nets_17" [InNet('1V2')] p7: voltage=0.000
SupplyNets "Schematic Supply Nets_16" [InNet('GVDD1')] p8: voltage=0.000
SupplyNets "Schematic Supply Nets_15" [InNet('VDDA')] p9: voltage=0.000
SupplyNets "Schematic Supply Nets_14" [InNet('5V')] p10: voltage=0.000
SupplyNets "Schematic Supply Nets_12" [InNet('3V3')] p11: voltage=0.000
SupplyNets "Schematic Supply Nets_11" [InNet('1V8')] p12: voltage=0.000
SupplyNets "Schematic Supply Nets_10" [InNet('AGND')] p13: voltage=0.000
SupplyNets "Schematic Supply Nets_9" [InNet('PHY0_VDDIO')] p14: voltage=0.000
SupplyNets "Schematic Supply Nets_8" [InNet('PHY0_VDDA')] p15: voltage=0.000
SupplyNets "Schematic Supply Nets_7" [InNet('VLDO')] p16: voltage=0.000
SupplyNets "Schematic Supply Nets_6" [InNet('GVDD6')] p17: voltage=0.000
SupplyNets "Schematic Supply Nets_5" [InNet('GVDD2')] p18: voltage=0.000
SupplyNets "Schematic Supply Nets_3" [InNet('VDDIO')] p19: voltage=0.000
SupplyNets "Schematic Supply Nets_2" [InNet('GVDD3')] p20: voltage=0.000
SupplyNets "Schematic Supply Nets_1" [InNet('EARTH')] p21: voltage=0.000
SupplyNets "Schematic Supply Nets" [InNet('3V3_VDDO')] p22: voltage=0.000
UnRoutedNet [All] p1: checkbadconnections=TRUE
Width USB_width [InNetClass('Analog')] p1: maxlimit=6.1 minlimit=4 preferedwidth=6
Width [All] p2: maxlimit=15 minlimit=3.5 preferedwidth=5 minimp=50.000000 maximp=50.000000 favimp=50.000000 checkconnectedcopper=TRUE
11 further rules are at their usual default settings.

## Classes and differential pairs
net class SPI_ENC: SPIA_CLK_AX1_2 SPIA_CLK_AX12 SPIA_PICO_AX1_2 SPIA_PICO_AX12 SPIA_POCI_AX12 SPIB_CLK_AX3_4 SPIB_CLK_AX34 SPIB_PICO_AX3_4 SPIB_PICO_AX34 SPIB_POCI_AX34 SPIC_CLK_AX5_6 SPIC_CLK_AX56 SPIC_PICO_AX5_6 SPIC_PICO_AX56 SPIC_POCI_AX56 SPID_CLK_DRV SPID_CLK_DRVCFG SPID_PICO_DRV SPID_PICO_DRVCFG SPID_POCI_DRV
net class PHY0_TX: ESC_TX0_CLK ESC_TX0_D0 ESC_TX0_D1 ESC_TX0_D2 ESC_TX0_D3
net class PHY0_RX: ESC_RX0_CLK ESC_RX0_D0 ESC_RX0_D1 ESC_RX0_D2 ESC_RX0_D3
net class "power rails": 1V2 1V8 3V3 3V3_VDDO 5V 5V_SYS 24V VDD VDDA VDDIO
component class TIDA-010992_12_Connectors: C202 C203 J10 J11 J12 J13 R210 R211 R212 R213 R214 R215 R216 R217 RT1 TP22 TP23 U16
component class TIDA-010992_11_DRV_AXIS6: C187 C188 C189 C190 C191 C192 C193 C194 C195 C196 C197 C198 C199 C200 C201 J9 R194 R195 R196 R197 R198 R199 R200 R201 R202 R203 R204 R205 R206 R207 R208 R209 U15
component class TIDA-010992_10_DRV_AXIS5: C172 C173 C174 C175 C176 C177 C178 C179 C180 C181 C182 C183 C184 C185 C186 J8 R178 R179 R180 R181 R182 R183 R184 R185 R186 R187 R188 R189 R190 R191 R192 R193 TP24 TP25 U14
component class TIDA-010992_09_DRV_AXIS4: C157 C158 C159 C160 C161 C162 C163 C164 C165 C166 C167 C168 C169 C170 C171 J7 R162 R163 R164 R165 R166 R167 R168 R169 R170 R171 R172 R173 R174 R175 R176 R177 U13
component class TIDA-010992_08_DRV_AXIS3: C142 C143 C144 C145 C146 C147 C148 C149 C150 C151 C152 C153 C154 C155 C156 J6 R146 R147 R148 R149 R150 R151 R152 R153 R154 R155 R156 R157 R158 R159 R160 R161 U12
component class TIDA-010992_07_DRV_AXIS2: C127 C128 C129 C130 C131 C132 C133 C134 C135 C136 C137 C138 C139 C140 C141 J5 R130 R131 R132 R133 R134 R135 R136 R137 R138 R139 R140 R141 R142 R143 R144 R145 U11
component class TIDA-010992_06_DRV_AXIS1: C112 C113 C114 C115 C116 C117 C118 C119 C120 C121 C122 C123 C124 C125 C126 J4 R112 R113 R114 R115 R116 R117 R118 R119 R120 R121 R122 R123 R124 R125 R127 R129 U10
component class TIDA-010992_05_ETH_Conn: C95 C96 C97 C98 C99 C100 C101 C102 C103 C104 C105 C106 C107 C108 C109 C110 C111 D5 D6 D7 J3 L9 L10 L11 L12 Q1 Q2 R78 R79 R80 R81 R98 R99 R100 R101 R102 R103 R104 R105 R106 R107 R108 R109 R110 R111 T1 T2 TP15 TP16 TP17 TP18 TP19 TP20 TP21 U8 U9
component class "TIDA-010992_04_BOOT_SoC power_CLK": C69 C70 C71 C72 C73 C74 C75 C76 C77 C78 C79 C80 C81 C82 C83 C84 C85 C86 C87 C88 C89 C90 C91 C92 C93 J2 L4 L5 L6 L7 R66 R67 R68 R69 R70 R71 R72 R73 R74 R75 R76 R82 R83 R84 R85 R86 R87 R88 R89 R90 R91 R92 R93 R94 R95 R96 R97 TP13 TP14 U6 U7
component class TIDA-010992_03_IO_Map_Debug: C42 C43 C44 C45 C46 C47 C48 C49 C50 C51 C52 C53 C54 C55 C56 C57 C58 C59 C60 C61 C62 C63 C64 C65 C66 C67 C68 C94 J1 J14 R17 R18 R19 R20 R21 R22 R23 R24 R25 R26 R27 R28 R29 R30 R31 R32 R33 R34 R35 R36 R37 R38 R39 R40 R41 R42 R43 R44 R45 R46 R47 R48 R49 R50 R51 R52 R53 R54 R55 R56 R57 R58 R59 R60 R61 R62 R63 R64 R65 R77 R126 R128 R218 R219 R222 SW1 TP12 U4 U5
component class TIDA-010992_02_Power: C1 C2 C3 C4 C5 C6 C7 C8 C9 C10 C11 C12 C13 C14 C15 C16 C17 C18 C19 C20 C21 C22 C23 C24 C25 C26 C27 C28 C29 C30 C31 C32 C33 C34 C35 C36 C37 C38 C39 C40 C41 D1 D2 D3 D4 DC+ GND L1 L2 L3 NT1 R1 R2 R3 R4 R5 R6 R7 R8 R9 R10 R11 R12 R13 R14 R15 R16 R220 R221 R223 TP1 TP2 TP3 TP4 TP5 TP6 TP7 TP8 TP9 TP10 TP11 U1 U2 U3
component class Header: J1 J2 J10 J11 J12 J13 J14
component class Logo: Logo2
component class TIDA-010992_Hardware: 1 FID1 FID2 FID3 LBL1 Logo1 Logo2 Logo3 Logo4 ZZ1 ZZ2 ZZ3 ZZ4
component class FiducialMark: FID1 FID2 FID3
component class AssemblyNote: ZZ1 ZZ2 ZZ3 ZZ4
component class Label: LBL1
differential pair T0_TD: +T0_TD_P -T0_TD_N
differential pair T0_RD: +T0_RD_P -T0_RD_N
differential pair PHY0_TD: +PHY0_TD_P -PHY0_TD_N
differential pair PHY0_RD: +PHY0_RD_P -PHY0_RD_N
differential pair H0_TD: +H0_TD_P -H0_TD_N
differential pair H0_RD: +H0_RD_P -H0_RD_N

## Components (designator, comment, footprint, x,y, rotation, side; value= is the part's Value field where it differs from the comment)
1 "CAUTION HOT SURFACE" IEC_HotSurface_Small 2335.15,1156.01 r270 bottom
C1 "GRM155R6YA105ME11D" 0402L 2126.46,896.22 r0 top value=1uF
C2 "C3216X5R1E476M160AC" 1206_190 2166.57,519.15 r0 top value=47uF
C3 "C3216X5R1E476M160AC" 1206_190 1982.37,519.15 r180 top value=47uF
C4 "GRM32ER71H106KA12L" 1210_270L 1060,2258 r90 bottom value=10uF
C5 "GRM32ER71H106KA12L" 1210_270L 1190,2259 r90 top locked value=10uF
C6 "GRM32ER71H106KA12L" 1210_270L 1320,2259 r90 top locked value=10uF
C7 "GRM32ER71H106KA12L" 1210_270L 1320,2258 r90 bottom value=10uF
C8 "GRM32ER71H106KA12L" 1210_270L 1060,2259 r90 top locked value=10uF
C9 "GRM32ER71H106KA12L" 1210_270L 1580,2258 r90 top locked value=10uF
C10 "885012205086" FP-885012205086_0402-MFG 2190.56,714.08 r90 top value=100nF
C11 "885012205086" FP-885012205086_0402-MFG 1919.72,714.39 r90 top value=100nF
C12 "C2012X7R1H475K125AC" FP-C2012X7R1H475K125AC_0805-MFG 2256.41,713.09 r90 top
C13 "C2012X7R1H475K125AC" FP-C2012X7R1H475K125AC_0805-MFG 1856.41,713.09 r90 top
C14 "885012205086" FP-885012205086_0402-MFG 2190.41,887.09 r270 top value=100nF
C15 "CGA2B2C0G1H220J050BA" 0402L 2011.67,956.14 r0 top value=22pF
C16 "GRM32ER71H106KA12L" 1210_270L 1190,2258 r90 bottom value=10uF
C17 "GRM32ER71H106KA12L" 1210_270L 1450,2258 r90 bottom value=10uF
C18 "GRM32ER71H106KA12L" 1210_270L 1450,2259 r90 top locked value=10uF
C19 "GRM32ER71H106KA12L" 1210_270L 631.69,2283.48 r0 bottom locked value=10uF
C20 "GRM32ER71H106KA12L" 1210_270L 1580,2258 r90 bottom value=10uF
C21 "CGA2B3X7R1H104M050BB" 0402 1662.48,662.99 r180 bottom value=0.1uF
C22 "CGA4J1X7R1E475K125AC" 0805L 1758.7,446.54 r90 bottom value=4.7uF
C23 "CGA4J1X7R1E475K125AC" 0805L 1759.35,445.25 r90 top value=4.7uF
C24 "CGA2B3X7R1H104M050BB" 0402 1701.81,444.84 r90 top value=0.1uF
C25 "GRM155C71A105KE11D" FP-GRM155C71A105KE11D_0402-MFG 1586.22,316.78 r0 top value=1µF
C26 "CGA2B3X7R1H104M050BB" 0402 1615.82,434.46 r90 bottom value=0.1uF
C27 "GRM033Z71C104KE14D" 0201 1688.5,447.04 r270 bottom value=0.1uF
C28 "CGA4J3X7S1A106K125AE" FP-CGA4J3X7S1A106K125AE_0805-MFG 1475.77,612.71 r180 top
C29 "CGA2B3X7R1H104M050BB" 0402 1566.06,600.53 r90 top value=0.1uF
C30 "GRM155C71A105KE11D" FP-GRM155C71A105KE11D_0402-MFG 1622.77,559.09 r0 top value=1µF
C31 "CGA2B3X7R1H104M050BB" 0402 1759.7,287.06 r0 bottom value=0.1uF
C32 "CGA4J3X7S1A106K125AE" FP-CGA4J3X7S1A106K125AE_0805-MFG 1764.06,299.28 r0 top
C33 "CGA2B3X7R1H104M050BB" 0402 1411.49,316.51 r270 bottom value=0.1uF
C34 "CGA4J3X7S1A106K125AE" FP-CGA4J3X7S1A106K125AE_0805-MFG 1415.26,333.68 r270 top
C35 "CGA4J3X7S1A106K125AE" FP-CGA4J3X7S1A106K125AE_0805-MFG 1372.06,471.94 r90 top
C36 "CGA2B3X7R1H104M050BB" 0402 1431.03,461.49 r90 top value=0.1uF
C37 "CGA2B3X7R1H104M050BB" 0402 1463.42,598.71 r270 bottom value=0.1uF
C38 "CGA4J3X7S1A106K125AE" FP-CGA4J3X7S1A106K125AE_0805-MFG 1403.37,595.17 r270 bottom
C39 "GRM155C71A105KE11D" FP-GRM155C71A105KE11D_0402-MFG 1499.26,305.3 r90 top value=1µF
C40 "GRM033Z71C104KE14D" 0201 1540.97,305.46 r90 top value=0.1uF
C41 "CGA2B3X7R1H104M050BB" 0402 1456.71,550.58 r180 top value=0.1uF
C42 "885012205037" 0402 385.77,1485.01 r180 top value=0.1uF
C43 "885012205037" 0402 1745.18,845.64 r0 bottom value=0.1uF
C44 "GRM188R61C475KAAJ" 0603 1096.11,880.78 r270 bottom value=4.7uF
C45 "GRM188R61A226ME15D" 0603 1679.88,1039.32 r180 bottom value=22uF
C46 "GRM033R71E681KA01D" 0201 898.97,459.07 r270 top value=680pF
C47 "GRM033R71E681KA01D" 0201 820.17,456.3 r270 top value=680pF
C48 "GRM188R61C475KAAJ" 0603 1581.15,1024.94 r90 bottom value=4.7uF
C49 "GRM188R61C475KAAJ" 0603 1315.08,988.03 r0 top value=4.7uF
C50 "GRM033R71E681KA01D" 0201 1304.33,924.63 r0 bottom value=680pF
C51 "GRM033R71E681KA01D" 0201 1305.41,875.41 r0 bottom value=680pF
C52 "GRM033R71E681KA01D" 0201 1304.31,971.9 r0 bottom value=680pF
C53 "GRM033R71E681KA01D" 0201 1169.28,766.4 r90 top value=680pF
C54 "GRM033R71E681KA01D" 0201 1057.56,821.46 r270 top value=680pF
C55 "GRM033R71E681KA01D" 0201 1081.21,821.35 r270 top value=680pF
C56 "GRM033R71E681KA01D" 0201 1310.33,854.02 r0 top value=680pF
C57 "GRM033R71E681KA01D" 0201 1299,805.65 r0 top value=680pF
C58 "GRM033R71E681KA01D" 0201 1282.45,901.23 r0 top value=680pF
C59 "GRM033R71E681KA01D" 0201 1310.18,995.39 r0 bottom value=680pF
C60 "GRM033R71E681KA01D" 0201 1303.93,1110.26 r0 top value=680pF
C61 "GRM033R71E681KA01D" 0201 1303.13,1059.05 r0 top value=680pF
C62 "GRM033R71E681KA01D" 0201 925.24,821.78 r270 top value=680pF
C63 "GRM033R71E681KA01D" 0201 984.68,819.52 r270 top value=680pF
C64 "GRM033R71E681KA01D" 0201 1311.47,1042.81 r0 bottom value=680pF
C65 "GRM033R71E681KA01D" 0201 1027.17,725.45 r270 top value=680pF
C66 "GRM033R71E681KA01D" 0201 1309.59,1132.39 r0 bottom value=680pF
C67 "GRM033R71E681KA01D" 0201 1309.94,1184.5 r0 bottom value=680pF
C68 "GRM188R61C475KAAJ" 0603 1191.15,825.58 r180 top value=4.7uF
C69 "GRM033Z71C104KE14D" 0201 533.58,1355.39 r180 top value=0.1uF
C70 "GRM033Z71C104KE14D" 0201 650.24,1397.28 r0 top value=0.1uF
C71 "GRM033Z71C104KE14D" 0201 715.3,1292.09 r0 top value=0.1uF
C72 "GRM033Z71C104KE14D" 0201 520.59,1331.76 r180 top value=0.1uF
C73 "GRM033Z71C104KE14D" 0201 546.93,1269.61 r270 top value=0.1uF
C74 "GRM155R71E104KE14D" 0402 1196.05,380.51 r0 top value=0.1uF
C75 "GRM188R61C106KAALD" 0603 1068.8,785.26 r0 bottom value=10uF
C76 "GRM033Z71C104KE14D" 0201 1022.77,1069.34 r0 bottom value=0.1uF
C77 "GRM033Z71C104KE14D" 0201 1058.48,1118.09 r280 bottom value=0.1uF
C78 "GRM033Z71C104KE14D" 0201 1086.97,1094.78 r270 bottom value=0.1uF
C79 "GRM033Z71C104KE14D" 0201 1029.57,1018.36 r90 bottom value=0.1uF
C80 "GRM188R61C106KAALD" 0603 1102.63,689.52 r90 bottom value=10uF
C81 "885012106018" 0603 1206.37,769.15 r180 bottom value=2.2uF
C82 "GRM155R61C225KE11D" 0402 1256.8,1063.86 r90 bottom value=2.2uF
C83 "GRM155R61C225KE11D" 0402 1197.98,892.16 r0 bottom value=2.2uF
C84 "885012106018" 0603 877.79,731.79 r90 bottom value=2.2uF
C85 "885012106018" 0603 882.49,844.51 r180 bottom value=2.2uF
C86 "GRM033Z71C104KE14D" 0201 1024.75,1108.29 r310 bottom value=0.1uF
C87 "GRM033Z71C104KE14D" 0201 1057.05,1172.07 r90 bottom value=0.1uF
C88 "GRM033Z71C104KE14D" 0201 1097.42,1056.67 r180 bottom value=0.1uF
C89 "GRM033Z71C104KE14D" 0201 949.97,1257.93 r0 bottom value=0.1uF
C90 "GRM033Z71C104KE14D" 0201 1004.96,856.21 r270 bottom value=0.1uF
C91 "GRM033Z71C104KE14D" 0201 1191.1,1078.52 r0 bottom value=0.1uF
C92 "GRM033Z71C104KE14D" 0201 980.15,856.04 r270 bottom value=0.1uF
C93 "GRM033Z71C104KE14D" 0201 963.38,1220.74 r90 bottom value=0.1uF
C94 "GRM033R71E681KA01D" 0201 1304.21,925.65 r0 top value=680pF
C95 "885012205037" 0402 341.58,734.59 r90 bottom value=0.1uF
C96 "GRM033Z71C104KE14D" 0201 692.69,1113.37 r90 top value=0.1uF
C97 "GRM033Z71C104KE14D" 0201 530.32,803.6 r270 top value=0.1uF
C98 "GRM0335C1H4R7BA01D" 0201_033 583.71,792.76 r270 bottom value=4.7pF
C99 "GRM0335C1H4R7BA01D" 0201_033 554.01,792.65 r270 bottom value=4.7pF
C100 "GRM0335C1H4R7BA01D" 0201_033 662.23,792.99 r270 bottom value=4.7pF
C101 "GRM0335C1H4R7BA01D" 0201_033 635.32,792.99 r270 bottom value=4.7pF
C102 "GRM188R60J476ME15D" 0603 686.1,1133.46 r90 bottom value=47uF
C103 "GRM033R71E103KE14D" 0201 667.44,1113.52 r90 top value=0.01uF
C104 "GRM188R61A226ME15D" 0603 504.6,769.57 r270 bottom value=22uF
C105 "GRM033R71E103KE14D" 0201 504.98,803.6 r270 top value=0.01uF
C106 "885012205037" 0402 672.37,679.95 r90 bottom value=0.1uF
C107 "1206Y2K00222KET" FP-1206Y2K00222KET_1206-MFG 429.26,631.58 r270 bottom value=2.2nF
C108 "CL05C220JB5NNNC" 0402 747.65,803.6 r270 top value=22pF
C109 "C1206C102KGRACAUTO" 1206_180 635.42,389.98 r270 bottom value=1000pF
C110 "C1005X5R1V225K050BC" 0402_065 423.14,790.61 r270 top value=2.2uF
C111 "GRM033Z71C104KE14D" 0201 380.67,807.48 r270 top value=0.1uF
C112 "CL31B106KBHNNNE" 1206_180 202.98,1959.18 r270 bottom value=10uF
C113 "C1005X7R1H104K050BE" 0402 220.57,1883.56 r270 top value=0.1uF
C114 "C1005X7R1H104K050BE" 0402 171.14,1883.56 r270 top value=0.1uF
C115 "CGA2B3X7R1H104M050BB" 0402 197.32,1971.72 r0 top value=0.1uF
C116 "CGA2B3X7R1H104M050BB" 0402 368.33,1620.38 r90 bottom value=0.1uF
C117 "GMC04X7R105K10NT" FP-GMC04X7R105K10NT_0402-MFG 374.71,1639.41 r90 top value=1µF
C118 "GRM0335C1E470JA01D" 0201_033 491.73,1647.2 r270 top value=47pF
C119 "GRM0335C1E470JA01D" 0201_033 514.74,1714.43 r270 top value=47pF
C120 "CGA2B3X7R1H104M050BB" 0402 231.05,1532.21 r180 bottom value=0.1uF
C121 "GRM0335C1E470JA01D" 0201_033 524.14,1757.3 r0 bottom value=47pF
C122 "GRM0335C1E470JA01D" 0201_033 537.15,1800.3 r270 bottom value=47pF
C123 "GRM0335C1E470JA01D" 0201_033 539.1,1862.92 r90 bottom value=47pF
C124 "GRM0335C1E470JA01D" 0201_033 526.14,1906.3 r0 bottom value=47pF
C125 "CGA2B3X7R1H104M050BB" 0402 395.08,2033.16 r270 top value=0.1uF
C126 "CGA2B3X7R1H104M050BB" 0402 306.14,2011.3 r270 top value=0.1uF
C127 "CL31B106KBHNNNE" 1206_180 754.56,1956.45 r270 bottom value=10uF
C128 "C1005X7R1H104K050BE" 0402 773.51,1880.22 r270 top value=0.1uF
C129 "C1005X7R1H104K050BE" 0402 721.8,1880.08 r270 top value=0.1uF
C130 "CGA2B3X7R1H104M050BB" 0402 746.96,1957.14 r0 top value=0.1uF
C131 "CGA2B3X7R1H104M050BB" 0402 924.58,1617.22 r90 bottom value=0.1uF
C132 "GMC04X7R105K10NT" FP-GMC04X7R105K10NT_0402-MFG 927.33,1635.77 r90 top value=1µF
C133 "GRM0335C1E470JA01D" 0201_033 1056.28,1671.78 r0 top value=47pF
C134 "GRM0335C1E470JA01D" 0201_033 1065.72,1729.08 r270 top value=47pF
C135 "CGA2B3X7R1H104M050BB" 0402 789.18,1529.79 r180 bottom value=0.1uF
C136 "GRM0335C1E470JA01D" 0201_033 1077.5,1755.16 r0 bottom value=47pF
C137 "GRM0335C1E470JA01D" 0201_033 1090.49,1796.42 r270 bottom value=47pF
C138 "GRM0335C1E470JA01D" 0201_033 1092.64,1862.03 r90 bottom value=47pF
C139 "GRM0335C1E470JA01D" 0201_033 1079.5,1903.23 r0 bottom value=47pF
C140 "CGA2B3X7R1H104M050BB" 0402 945.64,2033.42 r270 top value=0.1uF
C141 "CGA2B3X7R1H104M050BB" 0402 858.03,2020.06 r270 top value=0.1uF
C142 "CL31B106KBHNNNE" 1206_180 1322.91,1960.69 r270 bottom value=10uF
C143 "C1005X7R1H104K050BE" 0402 1284.11,1879.2 r270 top value=0.1uF
C144 "C1005X7R1H104K050BE" 0402 1333.69,1879.46 r270 top value=0.1uF
C145 "CGA2B3X7R1H104M050BB" 0402 1310.69,1957.13 r0 top value=0.1uF
C146 "CGA2B3X7R1H104M050BB" 0402 1477.58,1613.14 r90 bottom value=0.1uF
C147 "GMC04X7R105K10NT" FP-GMC04X7R105K10NT_0402-MFG 1484.27,1629.75 r90 top value=1µF
C148 "GRM0335C1E470JA01D" 0201_033 1625.74,1673.43 r90 top value=47pF
C149 "GRM0335C1E470JA01D" 0201_033 1637.61,1746.65 r0 top value=47pF
C150 "CGA2B3X7R1H104M050BB" 0402 1348.94,1532.68 r180 bottom value=0.1uF
C151 "GRM0335C1E470JA01D" 0201_033 1637.44,1754.61 r0 bottom value=47pF
C152 "GRM0335C1E470JA01D" 0201_033 1650.74,1797.05 r270 bottom value=47pF
C153 "GRM0335C1E470JA01D" 0201_033 1651.31,1861.89 r90 bottom value=47pF
C154 "GRM0335C1E470JA01D" 0201_033 1638.68,1904.78 r0 bottom value=47pF
C155 "CGA2B3X7R1H104M050BB" 0402 1507.71,2035.17 r270 top value=0.1uF
C156 "CGA2B3X7R1H104M050BB" 0402 1415.59,2018.79 r270 top value=0.1uF
C157 "CL31B106KBHNNNE" 1206_180 1862.59,2192.39 r270 bottom value=10uF
C158 "C1005X7R1H104K050BE" 0402 1876.15,2119.91 r270 top value=0.1uF
C159 "C1005X7R1H104K050BE" 0402 1826.68,2119.58 r270 top value=0.1uF
C160 "CGA2B3X7R1H104M050BB" 0402 1851.95,2198.21 r0 top value=0.1uF
C161 "CGA2B3X7R1H104M050BB" 0402 2021.14,1854.14 r90 bottom value=0.1uF
C162 "GMC04X7R105K10NT" FP-GMC04X7R105K10NT_0402-MFG 2032.02,1871.85 r90 top value=1µF
C163 "GRM0335C1E470JA01D" 0201_033 2147.78,1884.12 r270 top value=47pF
C164 "GRM0335C1E470JA01D" 0201_033 2170.2,1957.23 r270 top value=47pF
C165 "CGA2B3X7R1H104M050BB" 0402 1884.26,1770.77 r180 bottom value=0.1uF
C166 "GRM0335C1E470JA01D" 0201_033 2181.35,1996.22 r0 bottom value=47pF
C167 "GRM0335C1E470JA01D" 0201_033 2194.35,2035.59 r270 bottom value=47pF
C168 "GRM0335C1E470JA01D" 0201_033 2194.35,2098.58 r90 bottom value=47pF
C169 "GRM0335C1E470JA01D" 0201_033 2181.35,2144.69 r0 bottom value=47pF
C170 "CGA2B3X7R1H104M050BB" 0402 2047.42,2271.74 r270 top value=0.1uF
C171 "CGA2B3X7R1H104M050BB" 0402 1958.21,2258.8 r270 top value=0.1uF
C172 "CL31B106KBHNNNE" 1206_180 1843.88,1590.56 r270 bottom value=10uF
C173 "C1005X7R1H104K050BE" 0402 1852.79,1499.99 r270 top value=0.1uF
C174 "C1005X7R1H104K050BE" 0402 1801.89,1500.18 r270 top value=0.1uF
C175 "CGA2B3X7R1H104M050BB" 0402 1828.46,1578.69 r0 top value=0.1uF
C176 "CGA2B3X7R1H104M050BB" 0402 2001.92,1236.04 r90 bottom value=0.1uF
C177 "GMC04X7R105K10NT" FP-GMC04X7R105K10NT_0402-MFG 2008.99,1256.67 r90 top value=1µF
C178 "GRM0335C1E470JA01D" 0201_033 2124.44,1248.67 r270 top value=47pF
C179 "GRM0335C1E470JA01D" 0201_033 2148.13,1337.89 r270 top value=47pF
C180 "CGA2B3X7R1H104M050BB" 0402 1858.19,1152.56 r180 bottom value=0.1uF
C181 "GRM0335C1E470JA01D" 0201_033 2155.4,1380.31 r0 bottom value=47pF
C182 "GRM0335C1E470JA01D" 0201_033 2168.27,1422.1 r270 bottom value=47pF
C183 "GRM0335C1E470JA01D" 0201_033 2168.06,1482.51 r90 bottom value=47pF
C184 "GRM0335C1E470JA01D" 0201_033 2155.25,1526.34 r0 bottom value=47pF
C185 "CGA2B3X7R1H104M050BB" 0402 2027.83,1672 r270 top value=0.1uF
C186 "CGA2B3X7R1H104M050BB" 0402 1933.42,1630.08 r270 top value=0.1uF
C187 "CL31B106KBHNNNE" 1206_180 2371.89,1912.36 r270 bottom value=10uF
C188 "C1005X7R1H104K050BE" 0402 2329.96,1827.97 r270 top value=0.1uF
C189 "C1005X7R1H104K050BE" 0402 2380.09,1828.41 r270 top value=0.1uF
C190 "CGA2B3X7R1H104M050BB" 0402 2354.3,1905.66 r0 top value=0.1uF
C191 "CGA2B3X7R1H104M050BB" 0402 2525.93,1563.83 r90 bottom value=0.1uF
C192 "GMC04X7R105K10NT" FP-GMC04X7R105K10NT_0402-MFG 2535.54,1582.9 r90 top value=1µF
C193 "GRM0335C1E470JA01D" 0201_033 2654.96,1591.08 r270 top value=47pF
C194 "GRM0335C1E470JA01D" 0201_033 2678.78,1668.37 r270 top value=47pF
C195 "CGA2B3X7R1H104M050BB" 0402 2388.37,1480.04 r180 bottom value=0.1uF
C196 "GRM0335C1E470JA01D" 0201_033 2681.69,1707.62 r0 bottom value=47pF
C197 "GRM0335C1E470JA01D" 0201_033 2694.68,1745.1 r270 bottom value=47pF
C198 "GRM0335C1E470JA01D" 0201_033 2694.68,1810.57 r90 bottom value=47pF
C199 "GRM0335C1E470JA01D" 0201_033 2681.69,1855.16 r0 bottom value=47pF
C200 "CGA2B3X7R1H104M050BB" 0402 2550.75,1996.01 r270 top value=0.1uF
C201 "CGA2B3X7R1H104M050BB" 0402 2463.32,1962.59 r270 top value=0.1uF
C202 "GRM033R60J333KE01D" 0201 2337.52,896.17 r0 top value=0.033uF
C203 "885012205037" 0402 861.14,415.8 r0 bottom value=0.1uF
D1 "SMBJ33CA-13-F" SMB-Bi 631.69,2283.48 r0 top locked value=33V
D2 "150040GS73240" WL-SMCC_0402_Green 1896.82,325.1 r90 top value=Green
D3 "150040GS73240" WL-SMCC_0402_Green 1840,277 r270 top value=Green
D4 "150040GS73240" WL-SMCC_0402_Green 1630.66,726.34 r270 top value=Green
D5 "150040GS73240" WL-SMCC_0402_Green 357.16,946.03 r0 top value=Green
D6 "150040RS73220" FP-150040RS73220_0402-MFG 241.25,1190.58 r0 top
D7 "150040GS73240" WL-SMCC_0402_Green 301.68,1032.55 r0 top value=Green
DC+ "MTG_Pads" MTGP_2-48_PanHead 883.92,2279.14 r180 top locked
FID1 "Fiducial" Fiducial10-20 2748.76,2153.07 r180 bottom
FID2 "Fiducial" Fiducial10-20 2748.76,2153.34 r0 top
FID3 "Fiducial" Fiducial10-20 526.5,129.66 r0 top
GND "MTG_Pads" MTGP_2-48_PanHead 369.74,2279.14 r180 top locked
J1 "GRPB061VWVN-RC" Sullins_GRPB061VWVN-RC 1136.65,82.68 r180 top
J2 "GRPB021VWVN-RC" Sullins_GRPB021VWVN-RC 469.52,1229.6 r0 top
J3 "BM04B-GHS-TBT(LF)(SN)" FP-BM04B-GHS-TBT(LF)(SN)_HDR4-MFG 630.36,314.78 r0 top locked
J4 "12FHT-SM1-GAN-TF(HF)" FP-12FHT-SM1-GAN-TF(HF)_CONN_FPC_12-MFG 232.14,1709.3 r270 bottom
J5 "12FHT-SM1-GAN-TF(HF)" FP-12FHT-SM1-GAN-TF(HF)_CONN_FPC_12-MFG 788.05,1707.84 r270 bottom
J6 "12FHT-SM1-GAN-TF(HF)" FP-12FHT-SM1-GAN-TF(HF)_CONN_FPC_12-MFG 1349.09,1709.42 r270 bottom
J7 "12FHT-SM1-GAN-TF(HF)" FP-12FHT-SM1-GAN-TF(HF)_CONN_FPC_12-MFG 1885.29,1947.01 r270 bottom
J8 "12FHT-SM1-GAN-TF(HF)" FP-12FHT-SM1-GAN-TF(HF)_CONN_FPC_12-MFG 1858.08,1331.1 r270 bottom
J9 "12FHT-SM1-GAN-TF(HF)" FP-12FHT-SM1-GAN-TF(HF)_CONN_FPC_12-MFG 2388.69,1656.51 r270 bottom
J10 "GRPB031VWVN-RC" Sullins_GRPB031VWVN-RC 1818.35,82.68 r0 top
J11 "GRPB031VWVN-RC" Sullins_GRPB031VWVN-RC 1615.82,82.68 r0 top
J12 "GRPB031VWVN-RC" Sullins_GRPB031VWVN-RC 864,82.68 r0 top
J13 "GRPB031VWVN-RC" Sullins_GRPB031VWVN-RC 1416.62,82.68 r0 top
J14 "GRPB031VWVN-RC" Sullins_GRPB031VWVN-RC 1014.58,468.46 r180 top
L1 "TFM201610ALMA1R5MTAA" TFM201610ALMA 1681.64,367.71 r270 bottom value=1.5uH
L2 "TFM201610GHM-1R0MTAA" TFM201610 1410.13,420.49 r270 bottom value=1uH
L3 "TFM201610GHM-1R0MTAA" TFM201610 1533.71,600.6 r90 bottom value=1uH
L4 "7427927170" 0402 657.63,1382.77 r180 bottom value="75 ohm"
L5 "BLM18SG221TN1D" 0603 1039.86,689.52 r90 bottom value="220 ohm"
L6 "742792602" 0603 1199.63,833.15 r180 bottom value="60 ohm"
L7 "742792602" 0603 941.54,731.61 r90 bottom value="60 ohm"
L9 "7427927370" 0402 628.2,1129.91 r90 bottom value="70 ohm"
L10 "7427927370" 0402 395.99,812.35 r180 bottom value="70 ohm"
L11 "744232222" FP-744232222_SMT4_3MM2_1MM6-MFG 478.16,517.48 r0 top
L12 "744232222" FP-744232222_SMT4_3MM2_1MM6-MFG 699.15,517.84 r0 top
LBL1 "THT-14-423-10" Label_650x200 4025.59,4143.7 r0 top
Logo1 "CE Mark" CE_Mark_5mm 2197.3,912.45 r180 bottom
Logo2 "Texas Instruments" TI_Symbol_Overlay_Small 1513.99,1366.3 r0 top
Logo3 "FCC disclaimer" FCC_disclaimer 1061.63,2014.68 r0 top
Logo4 "WEEE logo" WEEE_Minimum 2190.56,670.48 r180 bottom
NT1 "Net-Tie" Net-Tie7milsWide_20milsLong 2071.07,770.41 r90 top net-tie
Q1 "CSD13383F4" YJC0003A 244.46,1244 r180 top value=12V
Q2 "CSD13383F4" YJC0003A 298.97,1079.23 r180 top value=12V
R1 "CRCW0402681KFKED" 0402L 1933.48,787.98 r270 top value=681k
R2 "CRCW040251K1FKED" 0402L 1913.41,841.09 r0 top value=51.1k
R3 "CRCW040240K2FKED" 0402L 2011.64,924.38 r180 top value=40.2k
R4 "CRCW040210K0FKED" 0402L 2051.47,893.02 r180 top value=10.0k
R5 "CRCW040213K0FKED" 0402L 1979.41,885.09 r0 top value=13.0k
R6 "CRCW040210K0FKED" 0402L 1741.47,735.65 r90 bottom value=10.0k
R7 "CRCW04022K20JNED" 0402 1655,662.99 r0 top value=2.2k
R8 "CRCW040210K0FKED" 0402L 1930.21,365.31 r270 top value=10.0k
R9 "CRCW04022K20JNED" 0402 1753.22,237.93 r180 top value=2.2k
R10 "CRCW04025K23FKED" 0402 1781.87,731.45 r90 bottom value=5.23k
R11 "PMR03EZPJ000" 0603 1962.01,437.72 r0 top value=0
R12 "RC0201JR-070RL" "FP-RC0201JR-070RL_0201 (0603 Metric)-IPC_C" 1678.94,485.61 r0 bottom
R13 "RC0201JR-070RL" "FP-RC0201JR-070RL_0201 (0603 Metric)-IPC_C" 1622.17,332.38 r0 bottom
R14 "RC0201JR-070RL" "FP-RC0201JR-070RL_0201 (0603 Metric)-IPC_C" 1476.92,416.69 r180 bottom
R15 "CRCW040210K0FKED" 0402L 1696.22,526.05 r0 top value=10.0k
R16 "RC0201JR-070RL" "FP-RC0201JR-070RL_0201 (0603 Metric)-IPC_C" 1586.74,574.39 r90 bottom
R17 "ERJ-1GNJ220C" 0201 1027.07,341.7 r270 top value=22
R18 "ERJ-1GNJ220C" 0201 997.04,341.59 r270 top value=22
R19 "ERJ-1GNJ220C" 0201 722,939.33 r180 top value=22
R20 "CRCW04022K20FKED" 0402 1035.81,217.24 r180 top value=2.20k
R21 "ERJ-2RKF1002X" 0402 1036.01,164.43 r0 top value=10.0k
R22 "ERJ-2RKF1002X" 0402 1035.17,188.24 r0 bottom value=10.0k
R23 "ERJ-2RKF1002X" 0402 1035.76,138.02 r0 bottom value=10.0k
R24 "ERJ-1GNJ220C" 0201 1206.88,494.76 r180 top value=22
R25 "ERJ-1GNJ220C" 0201 1161.65,151.01 r90 bottom value=22
R26 "ERJ-1GNJ220C" 0201 1207.12,519.48 r180 top value=22
R27 "ERJ-1GNJ220C" 0201 948.36,1477.47 r180 top value=22
R28 "ERJ-1GNJ220C" 0201 1211.2,151.59 r90 bottom value=22
R29 "ERJ-1GNJ220C" 0201 1111.2,1349.88 r90 top value=22
R30 "ERJ-1GNJ220C" 0201 1312.6,1160.33 r0 top value=22
R31 "ERJ-1GNJ220C" 0201 1289.84,1032.59 r0 top value=22
R32 "ERJ-1GNJ220C" 0201 1083.05,1206.5 r90 bottom value=22
R33 "ERJ-2GE0R00X" 0402L 768.87,1242.31 r180 bottom value=0
R34 "ERJ-1GNJ220C" 0201 1244.46,1355.39 r90 top value=22
R35 "ERJ-1GNJ220C" 0201 1150.84,1349.88 r90 top value=22
R36 "ERJ-2GE0R00X" 0402L 844.05,1252.66 r180 bottom value=0
R37 "ERJ-1GNJ220C" 0201 900.37,1278.63 r90 top value=22
R38 "ERJ-1GNJ220C" 0201 1153.69,1255.33 r90 bottom value=22
R39 "ERJ-2GE0R00X" 0402L 1571.31,301.44 r270 bottom value=0
R40 "ERJ-1GNJ220C" 0201 1167.08,465.22 r0 top value=22
R41 "CRCW04022K20JNED" 0402 494.36,1484.46 r0 top value=2.2k
R42 "ERJ-1GNJ220C" 0201 1251.09,1258.97 r90 top value=22
R43 "ERJ3LWFR005V" 0603 1814.51,1039.4 r0 bottom value=0.005
R44 "RC0201FR-7D100RL" 0201 886.89,502.33 r0 top value=100
R45 "RC0201FR-7D100RL" 0201 845.26,455.78 r90 top value=100
R46 "ERJ-2GE0R00X" 0402L 1854.15,970.18 r90 top value=0
R47 "RG1608P-124-B-T5" 0603 1581.63,907.04 r90 bottom value=120k
R48 "RC0201FR-7D100RL" 0201 1304.66,900.32 r180 bottom value=100
R49 "RC0201FR-7D100RL" 0201 1311.15,829.53 r180 top value=100
R50 "RC0201FR-7D100RL" 0201 898.1,821.77 r90 top value=100
R51 "RC0201FR-7D100RL" 0201 1312.29,851.77 r180 bottom value=100
R52 "RC0201FR-7D100RL" 0201 1298.75,781.75 r180 top value=100
R53 "RC0201FR-7D100RL" 0201 1008.39,818.96 r90 top value=100
R54 "RC0201FR-7D100RL" 0201 1304.55,948.4 r180 bottom value=100
R55 "RC0201FR-7D100RL" 0201 1282.73,877.49 r180 top value=100
R56 "RC0201FR-7D100RL" 0201 1308.86,1067 r180 bottom value=100
R57 "RC0201FR-7D100RL" 0201 1208.81,755.28 r180 top value=100
R58 "RC0201FR-7D100RL" 0201 1312.11,1018.91 r180 bottom value=100
R59 "RC0201FR-7D100RL" 0201 1052.63,725.14 r90 top value=100
R60 "RC0201FR-7D100RL" 0201 1059.89,769.62 r180 top value=100
R61 "RC0201FR-7D100RL" 0201 1305.17,1133.92 r180 top value=100
R62 "RC0201FR-7D100RL" 0201 1309.51,1158.06 r180 bottom value=100
R63 "RC0201FR-7D100RL" 0201 1106.82,821.23 r90 top value=100
R64 "RC0201FR-7D100RL" 0201 1303.42,1084.52 r180 top value=100
R65 "RC0201FR-7D100RL" 0201 1309.26,1209.42 r180 bottom value=100
R66 "ERJ-2RKF1002X" 0402 361.96,1180.12 r90 top value=10.0k
R67 "CRCW040222K1FKED" 0402 437.83,1122.26 r90 top value=22.1k
R68 "RC0201FR-7D4K7L" 0201 1046.11,1330.39 r90 top value=4.70k
R69 "RC0201FR-7D4K7L" 0201 1542.56,312.18 r270 bottom value=4.70k
R70 "RC0201FR-072K2L" 0201 752.3,889.59 r270 top value=2.20k
R71 "RC0201FR-7D4K7L" 0201 1310.93,283.93 r0 top value=4.70k
R72 "RC0201FR-7D4K7L" 0201 1310.93,245.74 r0 top value=4.70k
R73 "CRCW040222R0JNED" 0402L 725.46,1355.07 r0 top value=22
R74 "CRCW040222R0JNED" 0402L 725.64,1326.8 r0 top value=22
R75 "ERJ-2GEJ102X" 0402 488.93,1162.35 r180 bottom value=1.0k
R76 "CRCW04020000Z0EDHP" 0402 659.3,1304.81 r270 bottom value=0
R77 "RC0201FR-7D100RL" 0201 1303.77,949.56 r0 top value=100
R78 "RC0201FR-072K49L" 0201 642.33,1056.82 r0 bottom value=2.49k
R79 "RC0201FR-072K49L" 0201 749.94,1076.66 r90 top value=2.49k
R80 "RC0201FR-072K49L" 0201 749.94,1076.37 r90 bottom value=2.49k
R81 "RK73H1HTTC1501F" 0201 402.41,911.38 r0 bottom value=1.50k
R82 "RC0201FS-7D10KL" 0201 532.52,1345.03 r180 bottom value=10.0k
R83 "RC0201FS-7D10KL" 0201 264.14,1539.05 r180 top value=10.0k
R84 "RC0201FS-7D10KL" 0201 824.01,1589.48 r180 top value=10.0k
R85 "RC0201FS-7D10KL" 0201 1364.94,1529.79 r180 top value=10.0k
R86 "RC0201FS-7D10KL" 0201 1920.21,1804.63 r180 top value=10.0k
R87 "RC0201FS-7D10KL" 0201 1880.94,1190.68 r180 top value=10.0k
R88 "RC0201FS-7D10KL" 0201 2401.19,1494.26 r180 top value=10.0k
R89 "RC0201FS-7D10KL" 0201 1403.37,168.04 r0 bottom value=10.0k
R90 "RC0201FS-7D10KL" 0201 579.65,1320.78 r270 bottom value=10.0k
R91 "ERJ-2RKF1002X" 0402 1273.54,342.42 r90 top value=10.0k
R92 "ERJ-2RKF1002X" 0402 1165.1,348.42 r180 bottom value=10.0k
R93 "ERJ-2RKF1002X" 0402 1164.6,294.44 r180 bottom value=10.0k
R94 "ERJ-2RKF1002X" 0402 1164.36,244.42 r180 bottom value=10.0k
R95 "ERJ-2RKF1002X" 0402 1020.74,346.19 r0 bottom value=10.0k
R96 "ERJ-2RKF1002X" 0402 1020.2,296.66 r0 bottom value=10.0k
R97 "ERJ-2RKF1002X" 0402 1057.14,244.66 r0 bottom value=10.0k
R98 "CRCW04020000Z0EDHP" 0402 537.02,622.33 r180 bottom value=0
R99 "CRCW040275R0FKED" 0402 587,537.91 r270 bottom value=75.0
R100 "CRCW04020000Z0EDHP" 0402 709.46,537.91 r270 bottom value=0
R101 "CRCW040275R0FKED" 0402 650.92,537.52 r270 bottom value=75.0
R102 "CRCW04020000Z0EDHP" 0402 388.61,867.65 r0 bottom value=0
R103 "CRCW04026K49FKED" 0402 665.96,898.8 r180 bottom value=6.49k
R104 "CRG0402F4K7" 0402 569.89,1164.95 r270 bottom value=4.70k
R105 "CRG0402F4K7" 0402 398.46,897.51 r0 top value=4.70k
R106 "CRCW04021K50FKED" 0402 388.61,947.91 r180 bottom value=1.50k
R107 "CRCW04021K00FKED" 0402 289.84,911.42 r90 top value=1.00k
R108 "RC0402FR-071KL" 0402 276.9,1134.04 r0 top value=1.00k
R109 "RC0402FR-071KL" 0402 340.68,990.14 r0 top value=1.00k
R110 "CRCW04020000Z0EDHP" 0402 351.48,1319.88 r180 top value=0
R111 "CRCW04020000Z0EDHP" 0402 365.19,1068.62 r90 top value=0
R112 "CRCW04021K00FKED" 0402 416.47,1620.57 r90 bottom value=1.00k
R113 "CRCW04021K00FKED" 0402 454.33,1634.62 r90 top value=1.00k
R114 "CRCW020120R0FNED" 0201_033 516.42,1647.36 r90 top value=20.0
R115 "CRCW020120R0FNED" 0201_033 540.86,1714.31 r90 top value=20.0
R116 "ERJ-1GNJ220C" 0201 122.04,1644.03 r90 bottom value=22
R117 "CRCW020120R0FNED" 0201_033 550.14,1783.3 r180 top value=20.0
R118 "CRCW020120R0FNED" 0201_033 550.14,1816.63 r180 top value=20.0
R119 "ERJ-1GNJ220C" 0201 312.14,1585.3 r90 bottom value=22
R120 "ERJ-1GNJ220C" 0201 527.24,1909.46 r180 top value=22
R121 "RC0201FR-7D4K7L" 0201 431.58,2009.54 r90 top value=4.70k
R122 "RC0201FR-7D4K7L" 0201 442.77,1535.17 r0 top value=4.70k
R123 "CRCW020120R0FNED" 0201_033 549.14,1850.1 r180 top value=20.0
R124 "CRCW04021K00FKED" 0402 395.08,2034.45 r270 bottom value=1.00k
R125 "CRCW020120R0FNED" 0201_033 549.14,1883.3 r180 top value=20.0
R126 "RC0201FR-07100KL" 0201 2201.54,1575.2 r270 bottom value=100k
R127 "RC0402FR-0715KL" 0402 306.14,1945.24 r270 bottom value=15.0k
R128 "RC0201FR-07100KL" 0201 1724.39,1212.41 r90 bottom value=100k
R129 "CRCW040210K0FKED" 0402L 306.14,2040.64 r270 bottom value=10.0k
R130 "CRCW04021K00FKED" 0402 973.12,1617.37 r90 bottom value=1.00k
R131 "CRCW04021K00FKED" 0402 1004.87,1632.08 r90 top value=1.00k
R132 "CRCW020120R0FNED" 0201_033 1056.28,1646.54 r180 top value=20.0
R133 "CRCW020120R0FNED" 0201_033 1094.96,1728.65 r90 top value=20.0
R134 "ERJ-1GNJ220C" 0201 681.51,1645.79 r90 bottom value=22
R135 "CRCW020120R0FNED" 0201_033 1101.5,1779.83 r180 top value=20.0
R136 "CRCW020120R0FNED" 0201_033 1102.61,1812.98 r180 top value=20.0
R137 "ERJ-1GNJ220C" 0201 865.14,1585 r90 bottom value=22
R138 "ERJ-1GNJ220C" 0201 1080.14,1905.11 r180 top value=22
R139 "RC0201FR-7D4K7L" 0201 984.19,2012.39 r90 top value=4.70k
R140 "RC0201FR-7D4K7L" 0201 1011.19,1645.3 r270 bottom value=4.70k
R141 "CRCW020120R0FNED" 0201_033 1102.61,1846.55 r180 top value=20.0
R142 "CRCW04021K00FKED" 0402 946.86,2036.66 r270 bottom value=1.00k
R143 "CRCW020120R0FNED" 0201_033 1102.61,1879.09 r180 top value=20.0
R144 "RC0402FR-0715KL" 0402 856.68,1953.49 r270 bottom value=15.0k
R145 "CRCW040210K0FKED" 0402L 856.47,2040.5 r270 bottom value=10.0k
R146 "CRCW04021K00FKED" 0402 1528.1,1612.92 r90 bottom value=1.00k
R147 "CRCW04021K00FKED" 0402 1565.38,1618.57 r90 top value=1.00k
R148 "CRCW020120R0FNED" 0201_033 1602.79,1613.82 r90 top value=20.0
R149 "CRCW020120R0FNED" 0201_033 1638.18,1720.82 r180 top value=20.0
R150 "ERJ-1GNJ220C" 0201 1241.73,1644.11 r90 bottom value=22
R151 "CRCW020120R0FNED" 0201_033 1661.82,1779.98 r180 top value=20.0
R152 "CRCW020120R0FNED" 0201_033 1661.82,1813.57 r180 top value=20.0
R153 "ERJ-1GNJ220C" 0201 1430.8,1585.59 r90 bottom value=22
R154 "ERJ-1GNJ220C" 0201 1637.64,1910.85 r180 top value=22
R155 "RC0201FR-7D4K7L" 0201 1543.82,2014.33 r90 top value=4.70k
R156 "RC0201FR-7D4K7L" 0201 1564.82,1626.82 r270 bottom value=4.70k
R157 "CRCW020120R0FNED" 0201_033 1662.65,1848.07 r180 top value=20.0
R158 "CRCW04021K00FKED" 0402 1507.71,2051.56 r270 bottom value=1.00k
R159 "CRCW020120R0FNED" 0201_033 1662.65,1880.31 r180 top value=20.0
R160 "RC0402FR-0715KL" 0402 1415.93,1945.89 r270 bottom value=15.0k
R161 "CRCW040210K0FKED" 0402L 1415.59,2033.53 r270 bottom value=10.0k
R162 "CRCW04021K00FKED" 0402 2071.84,1854.13 r90 bottom value=1.00k
R163 "CRCW04021K00FKED" 0402 2109.44,1867.14 r90 top value=1.00k
R164 "CRCW020120R0FNED" 0201_033 2174.08,1883.92 r90 top value=20.0
R165 "CRCW020120R0FNED" 0201_033 2196.78,1957.45 r90 top value=20.0
R166 "ERJ-1GNJ220C" 0201 1704.94,2012.39 r0 top value=22
R167 "CRCW020120R0FNED" 0201_033 2205.35,2021.81 r180 top value=20.0
R168 "CRCW020120R0FNED" 0201_033 2205.68,2055.27 r180 top value=20.0
R169 "ERJ-1GNJ220C" 0201 1964.95,1820.49 r90 bottom value=22
R170 "ERJ-1GNJ220C" 0201 2185.18,2149.65 r180 top value=22
R171 "RC0201FR-7D4K7L" 0201 2085.17,2250.74 r90 top value=4.70k
R172 "RC0201FR-7D4K7L" 0201 2070.28,1850.53 r270 top value=4.70k
R173 "CRCW020120R0FNED" 0201_033 2205.68,2088.74 r180 top value=20.0
R174 "CRCW04021K00FKED" 0402 2047.42,2271.74 r270 bottom value=1.00k
R175 "CRCW020120R0FNED" 0201_033 2206.16,2122.2 r180 top value=20.0
R176 "RC0402FR-0715KL" 0402 1958.86,2175.1 r270 bottom value=15.0k
R177 "CRCW040210K0FKED" 0402L 1958.86,2263.5 r270 bottom value=10.0k
R178 "CRCW04021K00FKED" 0402 2051.18,1235.83 r90 bottom value=1.00k
R179 "CRCW04021K00FKED" 0402 2085.32,1249.31 r90 top value=1.00k
R180 "CRCW020120R0FNED" 0201_033 2149.4,1248.54 r90 top value=20.0
R181 "CRCW020120R0FNED" 0201_033 2171.68,1338.2 r90 top value=20.0
R182 "ERJ-1GNJ220C" 0201 1750.59,1269.08 r90 bottom value=22
R183 "CRCW020120R0FNED" 0201_033 2180.31,1402.2 r180 top value=20.0
R184 "CRCW020120R0FNED" 0201_033 2180.31,1435.67 r180 top value=20.0
R185 "ERJ-1GNJ220C" 0201 1934.75,1199.69 r90 bottom value=22
R186 "ERJ-1GNJ220C" 0201 2157.74,1531.35 r180 top value=22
